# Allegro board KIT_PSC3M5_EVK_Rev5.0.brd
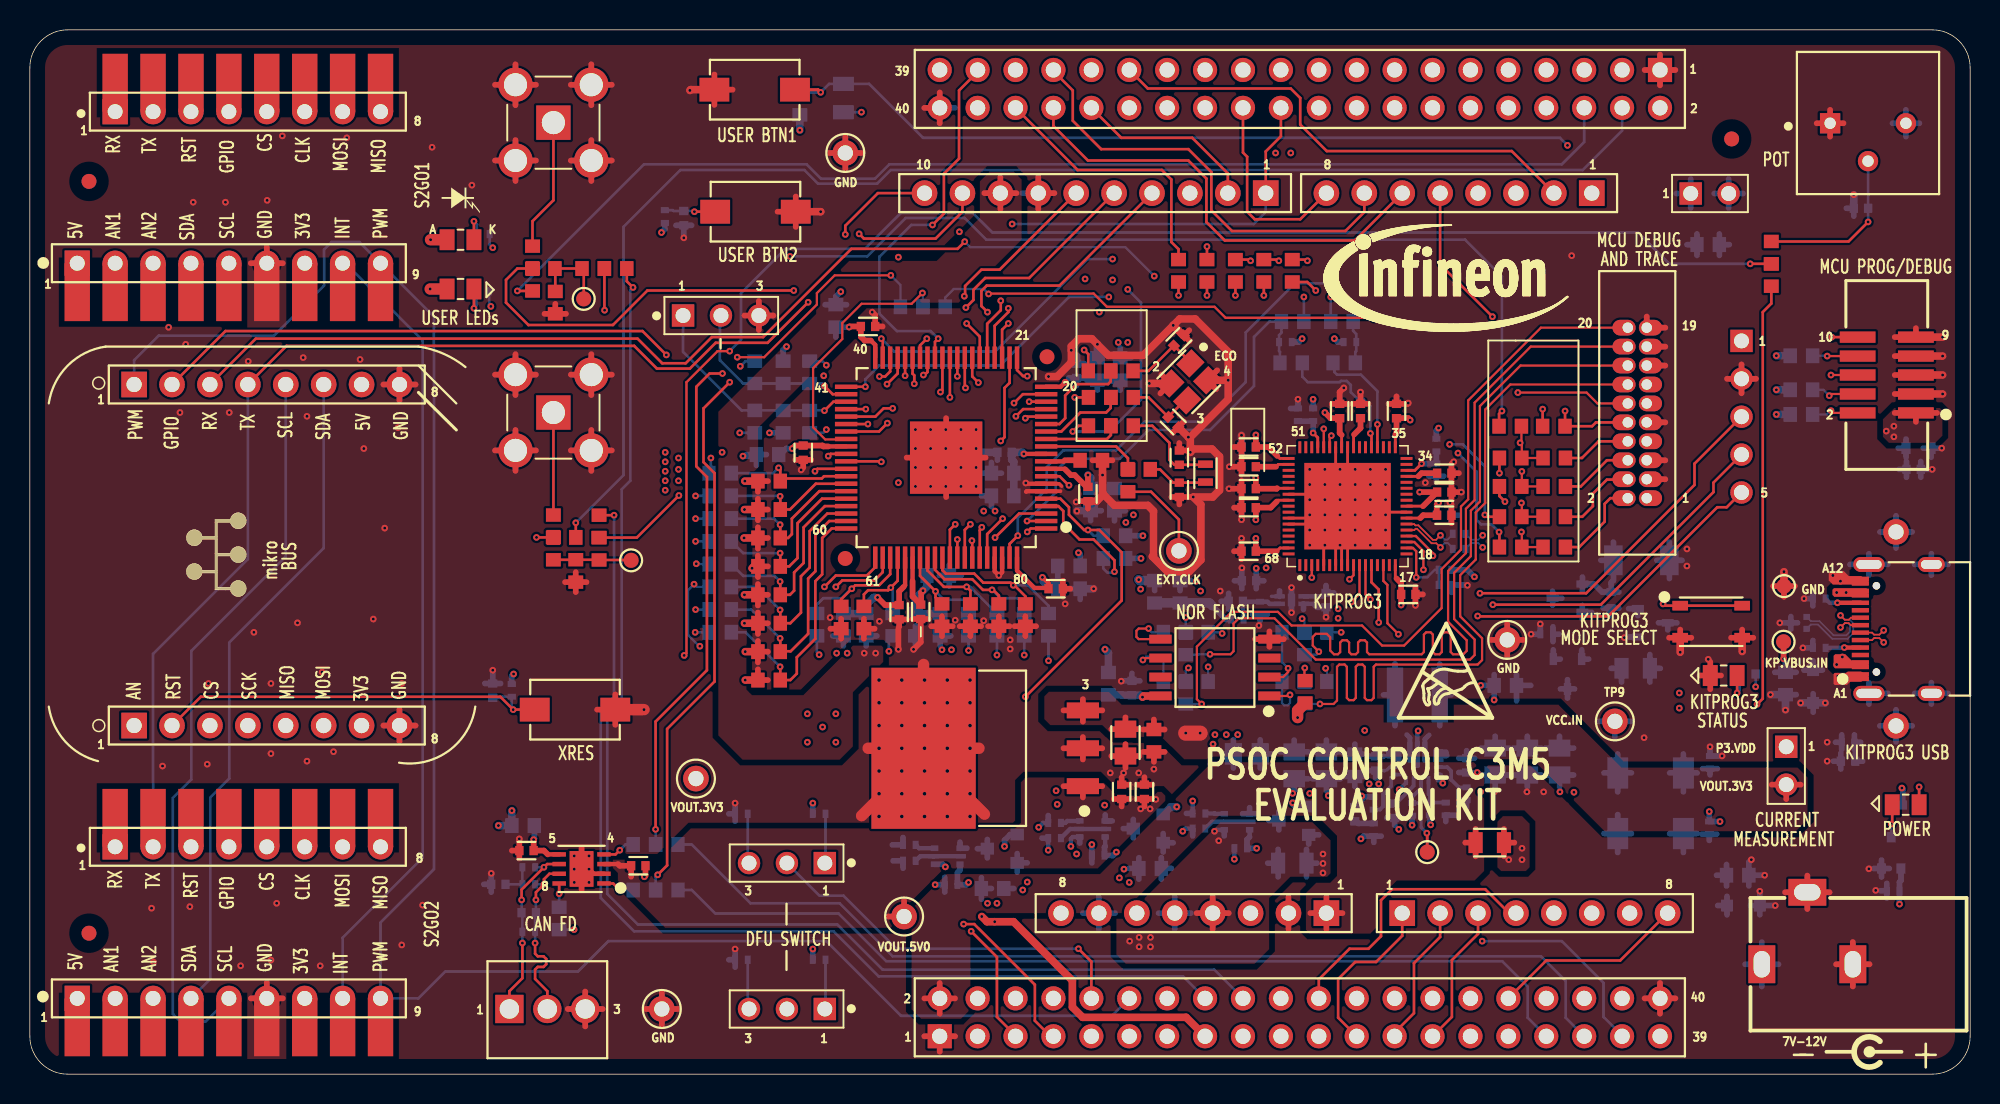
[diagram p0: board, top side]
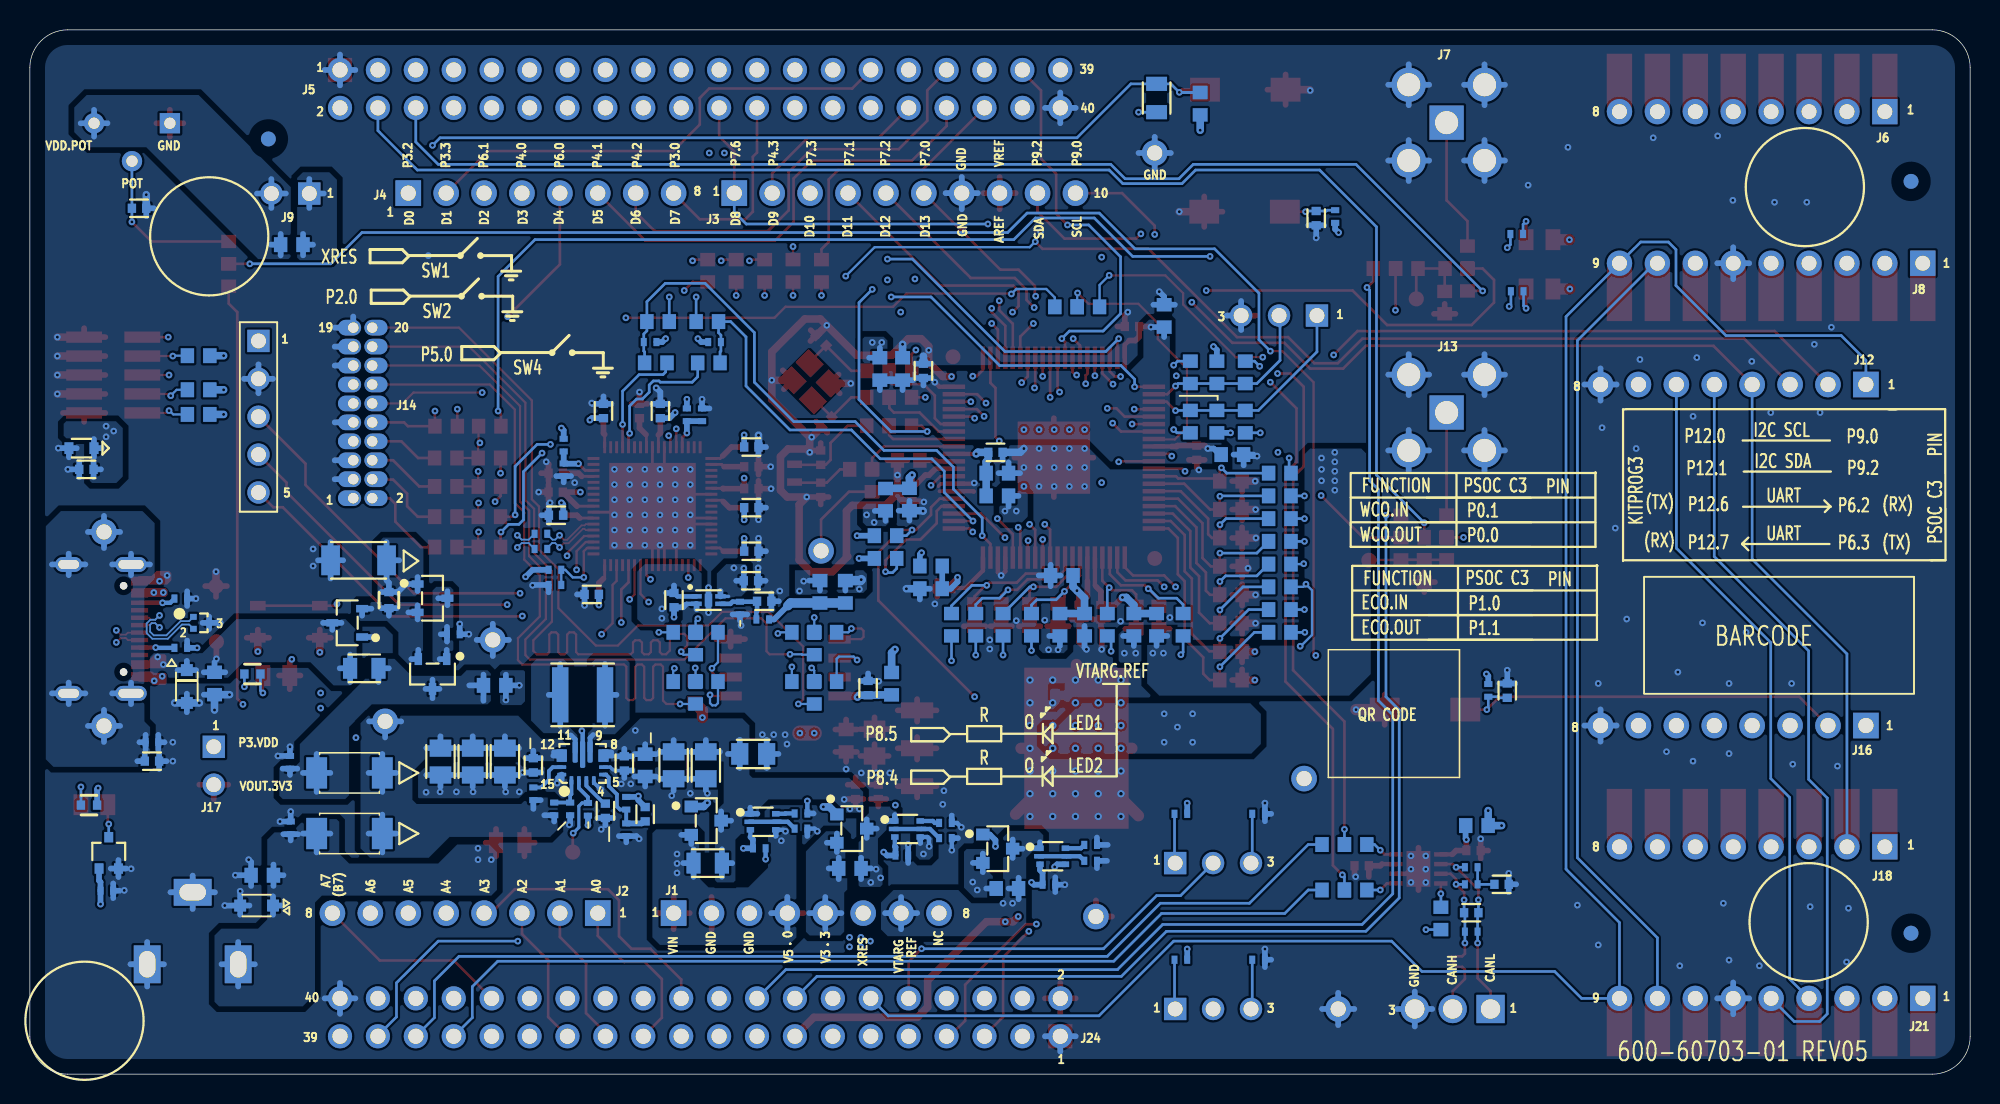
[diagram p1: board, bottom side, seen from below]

Outline 130 x 70 mm; copper layers: TOP, L02_GND, L03_SIG1, L04_SIG2, L05_PWR, BOTTOM. Coordinates in mm from the lower left corner of the outline.
Outline path: 0,67.46 0,2.54 arc(0.74,0.74) 2.54,0 127.46,0 arc(129.26,0.74) 130,2.54 130,67.46 arc(129.26,69.26) 127.46,70 2.54,70 arc(0.74,69.26) 0,67.46

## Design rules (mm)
constraint set DEFAULT: min track width 0.178
net group DIFFPAIR0: nets KP_USB_DM KP_USB_DP
net group DP1: nets N22087991 N22087993
net group POWER_PH: nets P5LP_VCCD P5LP_VDD
net group CS_MOSI_MISO_SPICLKMCU: nets CS MISO MOSI SPI_CLK_MCU
net group ETM: nets ETM_TRACE_CLK ETM_TRACE_D0 ETM_TRACE_D1 ETM_TRACE_D2 ETM_TRACE_D3
net group SPI_FLASH: nets SPI_CLK_FLASH SPI_CS_FLASH SPI_MISO_FLASH SPI_MOSI_FLASH
nets with their own width: min track width 0.178; nets P5LP_SWCLK P5LP_SWDIO
nets with their own width: min track width 0.254; nets GND_EARTH HDR_3V3 P5LP_SIO_VREF VDD_POT VDDA VIN VTARG_MEAS
nets with their own width: min track width 0.635; nets KP_VBUS
nets with their own width: min track width 0.762; nets GND_SIGNAL HDR_5V0 VDDD VOUT_3V3 VREFH VTARG_DEBUG VTARG_REF
nets with their own width: min track width 2.007; nets VIN_EXP

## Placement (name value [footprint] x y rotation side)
C1  1uF  [CAPC1608_0603N]  35.2 51.71 90 top
C2  0.1uF  [CAPC1005_0402N]  56.16 50.12 0 top
C3  18pF  [CAPC1005_0402N]  76.99 49.17 45 top
C4  0.1uF  [CAPC1005_0402N]  87.76 44.45 90 top
C5  1uF  [CAPC1005_0402N]  89.15 44.45 90 top
C6  0.1uF  [CAPC1005_0402N]  91.57 44.45 90 top
C7  18pF  [CAPC1005_0402N]  76.61 43.71 135 top
C8  0.1uF  [CAPC1005_0402N]  81.66 42.04 180 top
C9  0.1uF  [CAPC1005_0402N]  51.82 41.66 270 top
C10  22pF  [CAPC1005_0402N]  77.01 41.33 270 top
C11  4.7uF  [CAPC1608_0603N]  71.12 41.15 0 top
C12  1uF  [CAPC1005_0402N]  81.66 40.72 180 top
C13  1uF  [CAPC1005_0402N]  94.77 40.28 0 top
C14  0.1uF  [CAPC1608_0603N]  49.53 39.75 0 top
C15  0.1uF  [CAPC1005_0402N]  81.66 39.24 180 top
C16  22pF  [CAPC1005_0402N]  77.01 39.17 90 top
C17  1uF  [CAPC1005_0402N]  94.77 39.01 0 top
C18  0.1uF  [CAPC1005_0402N]  70.89 38.89 270 top
C19  0.1uF  [CAPC1608_0603N]  49.53 37.85 0 top
C20  0.1uF  [CAPC1005_0402N]  81.66 37.97 180 top
C21  0.1uF  [CAPC1005_0402N]  94.77 37.47 0 top
C22  0.1uF  [CAPC1608_0603N]  49.53 35.94 0 top
C23  0.1uF  [CAPC1005_0402N]  81.66 35.05 180 top
C24  0.1uF  [CAPC1608_0603N]  49.53 34.04 0 top
C25  1uF  [CAPC1608_0603N]  36.58 33.73 90 top
C26  0.1uF  [CAPC1608_0603N]  49.53 32.13 0 top
C27  0.1uF  [CAPC1005_0402N]  68.73 32.54 0 top
C28  0.1uF  [CAPC1005_0402N]  92.35 32.16 0 top
C29  0.1uF  [CAPC1608_0603N]  49.53 30.23 0 top
C30  0.1uF  [CAPC1005_0402N]  59.69 30.99 270 top
C31  0.1uF  [CAPC1608_0603N]  54.36 30.61 90 top
C32  0.1uF  [CAPC1608_0603N]  55.88 30.61 90 top
C33  0.1uF  [CAPC1608_0603N]  61.11 30.78 90 top
C34  0.1uF  [CAPC1608_0603N]  63.02 30.78 90 top
C35  0.1uF  [CAPC1608_0603N]  64.92 30.78 90 top
C36  0.1uF  [CAPC1608_0603N]  66.7 30.78 90 top
C37  0.22uF  [CAPC1005_0402N]  58.24 30.96 270 top
C38  0.1uF  [CAPC1608_0603N]  49.53 28.32 0 top
C39  0.1uF  [CAPC1608_0603N]  49.53 26.42 0 top
C40  0.1uF  [CAPC1005_0402N]  33.27 14.99 0 top
C41  0.1uF  [CAPC1005_0402N]  40.77 13.97 180 top
C42  0.1uF  [CAPC1005_0402N]  122.68 58.04 180 bottom
C43  0.1uF  [CAPC1005_0402N]  43.81 57.38 270 bottom
C44  1uF  [CAPC1608_0603N]  54 50.83 90 bottom
C45  1uF  [CAPC1608_0603N]  71.53 47.27 90 bottom
C46  0.1uF  [CAPC1005_0402N]  70.13 47.14 90 bottom
C47  1uF  [CAPC1005_0402N]  91.57 44.45 90 bottom
C48  1uF  [CAPC1005_0402N]  87.76 44.45 90 bottom
C49  1uF  [CAPC1005_0402N]  81.66 42.04 180 bottom
C50  0.1uF  [CAPC1005_0402N]  65.3 41.68 180 bottom
C51  1uF  [CAPC1608_0603N]  49.43 41.53 180 bottom
C52  1uF  [CAPC1005_0402N]  126.21 40.54 0 bottom
C53  1uF  [CAPC1608_0603N]  65.18 40.28 180 bottom
C54  10uF  [CAPC1608_0603N]  71.07 38.52 270 bottom
C55  1uF  [CAPC1005_0402N]  81.66 37.97 180 bottom
C56  1uF  [CAPC1005_0402N]  94.74 37.47 0 bottom
C57  1uF  [CAPC1005_0402N]  81.66 35.05 180 bottom
C58  0.1uF  [CAPC1005_0402N]  81.69 33.07 180 bottom
C59  1uF  [CAPC1608_0603N]  69.62 32.54 0 bottom
C60  1uF  [CAPC1005_0402N]  92.35 32.16 0 bottom
C61  0.1uF  [CAPC1005_0402N]  86.84 31.78 270 bottom
C62  0.1uF  [CAPC1005_0402N]  80.8 31.7 180 bottom
C63  10uF  [CAPC1608_0603N]  59.33 30.12 270 bottom
C65  10uF  [CAPC1608_0603N]  117.63 26.19 270 bottom
C66  0.1uF  [CAPC1005_0402N]  73.84 25.88 270 bottom
C67  0.1uF  [CAPC1005_0402N]  31.01 25.71 90 bottom
C79  10nF  [CAPC1005_0402N]  121.82 20.98 180 bottom
C80  10uF  [CAPC2012_0805N]  102.49 20.95 270 bottom
C81  10uF  [CAPC2012_0805N]  100.33 20.95 270 bottom
C82  10uF  [CAPC2012_0805N]  98.17 20.95 270 bottom
C83  0.1uF  [CAPC1005_0402N]  90.17 20.83 270 bottom
C84  0.1uF  [CAPC1005_0402N]  96.27 20.7 270 bottom
C85  10uF  [CAPC1608_0603N]  88.77 20.7 270 bottom
C86  22uF  [CAPC2012_0805N]  86.87 20.7 270 bottom
C87  22uF  [CAPC2012_0805N]  84.71 20.7 270 bottom
C88  22uF  [CAPC2012_0805N]  81.53 21.46 180 bottom
C90  0.1uF  [CAPC1005_0402N]  91.44 17.65 270 bottom
C91  22pF  [CAPC1005_0402N]  88.77 17.42 270 bottom
C92  1uF  [CAPC1608_0603N]  114.43 13.34 0 bottom
C93  100pF  [CAPC1005_0402N]  31.39 12.73 180 bottom
C94  100pF  [CAPC1005_0402N]  33.43 10.82 180 bottom
C95  0.47uF  [CAPC1005_0402N]  74.68 18.92 90 top
C96  1uF  [CAPC1005_0402N]  73.15 18.92 90 top
C97  10uF  [CAPC1608_0603N]  75.31 22.35 270 top
C98  33uF  [CAPC2012_0805N]  73.41 22.23 270 top
D1  ESD5V0D5-TP  [SODFL1608X77M]  126.54 41.96 180 bottom
D2  TLZ5V1A-GS08  [DIOMELF3515N]  107.98 34.44 0 bottom
D3  SD05-7  [DIO2_SOD323N]  119.48 25.98 90 bottom
D4  PMEG3030EP  [DIO_NXP_SOD-128]  108.58 20.19 0 bottom
D5  PMEG3030EP  [DIO_NXP_SOD-128]  108.58 16.13 0 bottom
D6  ESD12VD3B-TP  [DIO2_SOD323_BIQ]  114.81 11.3 180 bottom
FB1  1K  [INDC1608_0603N]  72.67 38.51 90 bottom
FB2  1K  [INDC1608_0603N]  60.99 30.12 90 bottom
J1  CON 8  [RTST254P1X08_W265]  86.87 10.79 180 top
J2  CON 8  [RTST254P1X08_W265]  91.95 10.79 0 top
J3  CON 10  [RTST254P1X10_W265]  82.8 59.05 180 top
J4  CON 8  [RTST254P1X08_W265]  104.65 59.05 180 top
J5  61304021821  [WURTH_61304021821]  109.22 67.31 180 top
J6  CON 8  [RTST254P1X08_W265_VER1]  5.71 64.52 0 top
J7  733910070  [MOL_SMA73391007X]  35.08 63.78 0 top
J8  CON 9  [SULLINS_PPPC091LFBN-RC_VER1]  3.17 54.36 0 top
J9  HDR 2  [CTST254P1X02_W260]  111.28 59.03 0 top
J10  HDR 3  [CTST254P1X03_W260]  43.76 50.85 0 top
J11  HDR 5x2  [FCI_20021521-00010T1LF]  126.36 44.32 90 top
J12  CON 8  [RTST254P1X08_W265]  6.99 46.23 0 top
J13  733910070  [MOL_SMA73391007X]  35.08 44.35 0 top
J14  HDR 10x2  [CNC_3220-20-0100-00]  108.33 38.61 90 top
J15  629722000214  [GCT_USB4105-GF-A]  126.32 29.85 90 top
J16  CON 8  [RTST254P1X08_W265]  6.99 23.37 0 top
J17  HDR 2  [CTST254P1X02_W260]  117.68 21.95 270 top
J18  CON 8  [RTST254P1X08_W265_VER1]  5.71 15.24 0 top
J19  HDR 3  [CTST254P1X03_W260]  53.26 14.15 180 top
J20  PWR_JACK  [CUI_PJ-102A]  116.04 7.37 0 top
J21  CON 9  [SULLINS_PPPC091LFBN-RC_VER1]  3.17 5.08 0 top
J22  HDR 3  [CTST254P1X03_W260]  53.26 4.37 180 top
J23  691210910003  [OST_OSTVN03A150]  32.13 4.37 0 top
J24  61304021821  [WURTH_61304021821]  60.96 2.54 0 top
J25  HDR 5  [CTST254P1X05_W260]  114.68 49.15 270 bottom
JMP1  USB_Hold  [CON_RA_STIFF_1000P]  125.03 23.35 90 top
L1  1.5uH  [PULSE_PA4332]  92.96 25.43 90 bottom
LED1  BLUE  [LEDC2012_0805_BLUE]  28.85 55.93 180 top
LED2  Yellow LED  [LEDC2012_0805]  28.85 52.63 180 top
LED3  Yellow LED  [LEDC2012_0805]  113.49 26.72 0 top
LED4  RED  [LEDC2012_0805]  125.68 18.06 0 top
NOREF  -  []  162.49 68.66 90 top
NOREF#2  -  []  54.69 46.08 0 top
NOREF#3  -  []  203.65 115.42 0 top
NOREF#4  -  []  124.02 -12.29 0 top
NOREF#5  -  []  56.83 16.64 90 top
NOREF#6  -  []  38.31 9.31 0 top
NOREF#7  -  []  60.96 2.54 90 top
NOREF#8  -  []  83.82 67.31 0 top
NOREF#9  -  []  122.64 28.1 90 top
NOREF#10  -  []  129.23 69.28 0 top
NOREF#11  -  []  60.96 67.31 0 top
NOREF#12  -  []  79.39 35.33 90 top
NOREF#13  -  []  38.31 9.31 0 top
NOREF#14  -  []  75.75 29.16 0 top
NOREF#15  -  []  56.83 16.64 0 top
NOREF#16  -  [unnamed#2]  3.96 59.84 0 top
NOREF#17  -  []  110.89 1.19 90 top
NOREF#18  -  []  35.46 14.73 0 top
NOREF#19  -  []  -9.63 -34.14 0 top
NOREF#20  -  []  -11.43 -23.16 0 top
NOREF#21  -  []  38.46 12.78 90 top
NOREF#22  -  []  83.82 2.54 0 top
NOREF#23  -  []  70.55 21.84 90 top
NOREF#24  -  []  63.37 18.9 0 top
NOREF#25  -  []  0 0 90 top
NOREF#26  -  []  122.65 25.38 0 top
NOREF#27  -  []  60.96 2.54 0 top
NOREF#28  -  []  123.22 25.53 0 top
NOREF#29  -  []  127.4 25.53 90 top
NOREF#30  -  []  119.38 71.12 0 top
NOREF#31  -  [unnamed#2]  114.02 62.69 0 top
NOREF#32  -  []  113.77 298.25 0 top
NOREF#33  -  []  110.89 73.89 0 top
NOREF#34  -  []  122.64 28.6 90 top
NOREF#35  -  []  76.76 24.61 90 top
NOREF#36  -  []  67.39 35.33 0 top
NOREF#37  -  []  131.59 18.03 90 top
NOREF#38  -  []  131.59 18.03 90 top
NOREF#39  -  []  83.05 26.62 90 top
NOREF#40  -  []  76.76 24.61 0 top
NOREF#41  -  []  59.29 6.43 0 top
NOREF#42  -  []  68.09 41.08 90 top
NOREF#43  -  []  0 70 0 top
NOREF#44  -  []  109.22 64.77 90 top
NOREF#45  -  []  -292.35 -210.03 0 top
NOREF#46  -  []  42.16 65 0 top
NOREF#47  -  []  58.1 21.84 0 top
NOREF#48  -  []  96.8 143.36 0 top
NOREF#49  -  [unnamed#2]  3.96 9.45 0 top
NOREF#50  -  []  -29.59 22.1 180 bottom
NOREF#51  -  [unnamed#2]  3.96 59.84 180 bottom
NOREF#52  -  []  -34.42 19.05 180 bottom
NOREF#53  -  [unnamed#2]  114.02 62.69 180 bottom
NOREF#54  -  [unnamed#2]  3.96 9.45 180 bottom
NOREF#55  -  []  -137.87 -9.3 180 bottom
NOREF#56  -  []  -98.83 1.05 180 bottom
Q1  PMV48XP,215  [SOT95P230X110-3N]  103.02 31.9 270 bottom
Q2  PMV48XP,215  [SOT95P230X110-3N]  108.74 30.25 90 bottom
Q3  PMV48XP,215  [SOT95P230X110-3N]  103.02 26.82 0 bottom
Q4  DMG2301L-7  [SOT23_G_S_D-DIODES]  84.68 16.99 270 bottom
Q5  DMG2301L-7  [SOT23_G_S_D-DIODES]  74.93 16.46 270 bottom
Q6  BCM857BV,115  [SOT666_6N-NXP]  80.87 16.92 270 bottom
Q7  BCM857BV,115  [SOT666_6N-NXP]  71.2 16.43 270 bottom
Q8  DMG2301L-7  [SOT23_G_S_D-DIODES]  65.15 15.11 270 bottom
Q9  BCM857BV,115  [SOT666_6N-NXP]  61.47 14.61 270 bottom
Q10  NX3020NAKW,115  [SOT323_SC70-3N_NXP]  124.71 14.83 180 bottom
R1  10K  [TRIM_3386P-1-103TLF]  120.62 63.74 0 top
R2  0 Ohm  [RESC1608_0603N]  116.68 55.07 270 top
R3  0 Ohm  [RESC1608_0603N]  116.68 53.57 90 top
R4  0 Ohm  [RESC1608_0603N]  33.68 54.75 270 top
R5  10K  [RESC1608_0603N]  34.43 54 180 top
R6  0 Ohm  [RESC1608_0603N]  37.74 54 180 top
R7  0 Ohm  [RESC1608_0603N]  39.24 54 180 top
R8  0 Ohm  [RESC1608_0603N]  33.68 53.25 90 top
R9  0 Ohm  [RESC1608_0603N]  78.87 53.85 270 top
R10  0 Ohm  [RESC1608_0603N]  77.45 25.56 90 bottom
R11  0 Ohm  [RESC1608_0603N]  80.77 53.85 270 top
R12  0 Ohm  [RESC1608_0603N]  85.4 28.87 90 bottom
R13  0 Ohm  [RESC1608_0603N]  71.67 47.14 0 top
R14  0 Ohm  [RESC1608_0603N]  73.17 47.14 0 top
R15  0 Ohm  [RESC1608_0603N]  82.68 53.85 270 top
R16  0 Ohm  [RESC1608_0603N]  77.45 28.87 90 bottom
R17  0 Ohm  [RESC1608_0603N]  71.68 45.36 180 top
R18  0 Ohm  [RESC1608_0603N]  73.18 45.36 180 top
R19  0 Ohm  [RESC1608_0603N]  84.58 53.85 270 top
R20  0 Ohm  [RESC1608_0603N]  85.4 25.56 90 bottom
R21  0 Ohm  [RESC1608_0603N]  71.68 43.46 180 top
R22  0 Ohm  [RESC1608_0603N]  73.18 43.46 0 top
R23  0 Ohm  [RESC1608_0603N]  76.96 53.85 270 top
R24  0 Ohm  [RESC1608_0603N]  60.58 51.44 180 bottom
R25  0 Ohm  [RESC1608_0603N]  102.11 43.43 180 top
R26  0 Ohm  [RESC1608_0603N]  74.32 40.54 0 top
R27  0 Ohm  [RESC1608_0603N]  73.57 39.79 270 top
R28  0 Ohm  [RESC1608_0603N]  99.21 41.3 0 top
R29  0 Ohm  [RESC1608_0603N]  102.13 41.3 180 top
R30  0 Ohm  [RESC1608_0603N]  99.21 39.4 0 top
R31  0 Ohm  [RESC1608_0603N]  102.13 39.4 180 top
R32  0 Ohm  [RESC1608_0603N]  35.08 36.73 270 top
R33  0 Ohm  [RESC1608_0603N]  38.14 36.72 270 top
R34  0 Ohm  [RESC1608_0603N]  35.83 35.98 180 top
R35  10K  [RESC1608_0603N]  35.08 35.23 90 top
R36  0 Ohm  [RESC1608_0603N]  38.14 35.22 270 top
R37  0 Ohm  [RESC1608_0603N]  99.21 37.36 0 top
R38  0 Ohm  [RESC1608_0603N]  102.13 37.36 180 top
R39  0 Ohm  [RESC1608_0603N]  99.21 35.33 0 top
R40  0 Ohm  [RESC1608_0603N]  102.13 35.33 180 top
R41  10K  [RESC1608_0603N]  85.45 25.63 90 top
R42  0 OHM  [RESC2012X60N]  97.82 15.52 180 top
R43  10K  [RESC1608_0603N]  51.59 65.05 90 bottom
R44  4.7K  [RESC1005_0402N]  42.55 57.49 90 bottom
R45  2.7K  [RESC1005_0402N]  30.38 56.31 0 bottom
R46  390 OHM  [RESC1005_0402N]  30.35 52.48 0 bottom
R47  0 Ohm  [RESC1608_0603N]  87.91 50.44 180 bottom
R48  0 Ohm  [RESC1608_0603N]  84.61 50.44 0 bottom
R49  0 Ohm  [RESC1608_0603N]  112.45 55.6 0 bottom
R50  4.7K  [RESC1005_0402N]  88.44 49.07 180 bottom
R51  4.7K  [RESC1005_0402N]  84.12 49.07 0 bottom
R52  10K  [RESC1608_0603N]  118.69 48.16 180 bottom
R53  0 Ohm  [RESC1608_0603N]  88.06 47.68 0 bottom
R54  0 Ohm  [RESC1608_0603N]  84.51 47.68 180 bottom
R55  0 Ohm  [RESC1608_0603N]  73.05 47.27 90 bottom
R56  0 Ohm  [RESC1608_0603N]  52.25 47.04 270 bottom
R57  10K  [RESC1608_0603N]  50.47 47.04 90 bottom
R58  0 Ohm  [RESC1608_0603N]  48.56 47.04 270 bottom
R59  10K  [RESC1608_0603N]  118.69 45.87 180 bottom
R60  10K  [RESC1608_0603N]  118.69 44.22 180 bottom
R61  49.9K  [RESC1005_0402N]  85.98 44.2 270 bottom
R62  49.9K  [RESC1005_0402N]  84.96 44.2 270 bottom
R63  0 Ohm  [RESC1608_0603N]  52.25 43.74 90 bottom
R64  10K  [RESC1608_0603N]  50.47 43.74 270 bottom
R65  0 Ohm  [RESC1608_0603N]  48.56 43.74 90 bottom
R66  15K  [RESC1005_0402N]  94.23 42.16 270 bottom
R67  30K  [RESC1005_0402N]  94.23 40.51 90 bottom
R68  0 Ohm  [RESC1608_0603N]  46.25 40.28 180 bottom
R69  0 Ohm  [RESC1608_0603N]  65.18 38.76 180 bottom
R70  0 Ohm  [RESC1608_0603N]  46.25 38.76 180 bottom
R71  0 Ohm  [RESC1608_0603N]  46.25 37.24 180 bottom
R72  22 OHM  [RESC1005_0402N]  95.76 36.22 180 bottom
R73  10K  [RESC1608_0603N]  72.67 36.09 180 bottom
R74  0 Ohm  [RESC1608_0603N]  46.25 35.71 180 bottom
R75  22 OHM  [RESC1005_0402N]  95.76 35.2 180 bottom
R76  10K  [RESC1608_0603N]  72.67 34.57 180 bottom
R77  0 Ohm  [RESC1608_0603N]  46.25 34.19 180 bottom
R78  0 Ohm  [RESC1608_0603N]  69.62 34.06 0 bottom
R79  15K  [RESC1005_0402N]  94.82 33.81 180 bottom
R80  0 Ohm  [RESC1608_0603N]  60.86 33.43 0 bottom
R81  30K  [RESC1005_0402N]  94.82 32.79 180 bottom
R82  0 Ohm  [RESC1608_0603N]  46.25 32.66 180 bottom
R83  5.1K  [RESC1005_0402N]  119.89 31.88 180 bottom
R84  330 OHM  [RESC1005_0402M]  105.94 31.78 270 bottom
R85  0 Ohm  [RESC1608_0603N]  46.25 31.14 180 bottom
R86  100K  [RESC1005_0402N]  80.9 30.48 180 bottom
R87  0 Ohm  [RESC1608_0603N]  68.25 30.12 270 bottom
R88  0 Ohm  [RESC1608_0603N]  66.62 30.12 270 bottom
R89  0 Ohm  [RESC1608_0603N]  64.8 30.12 270 bottom
R90  0 Ohm  [RESC1608_0603N]  62.89 30.12 270 bottom
R91  0 Ohm  [RESC1608_0603N]  57.81 30.12 270 bottom
R92  0 Ohm  [RESC1608_0603N]  56.03 30.12 90 bottom
R93  0 Ohm  [RESC1608_0603N]  54.51 30.12 90 bottom
R94  0 Ohm  [RESC1608_0603N]  52.73 30.12 270 bottom
R95  0 Ohm  [RESC1608_0603N]  78.2 29.62 180 bottom
R96  33 OHM  [RESC1608_0603N]  76.7 29.62 180 bottom
R97  0 Ohm  [RESC1608_0603N]  46.25 29.62 180 bottom
R98  10K  [RESC1005_0402N]  101.63 29.49 0 bottom
R99  5.1K  [RESC1005_0402N]  119.89 28.57 180 bottom
R100  0 Ohm  [RESC1608_0603N]  78.2 26.31 180 bottom
R101  33 OHM  [RESC1608_0603N]  76.7 26.31 180 bottom
R102  0 OHM  [RESC2012X60N]  107.59 27.2 180 bottom
R104  0 Ohm  [RESC1608_0603N]  86.15 29.62 180 bottom
R105  33 OHM  [RESC1608_0603N]  84.65 29.62 180 bottom
R106  750 OHM  [RESC1005_0402M]  115.09 26.82 0 bottom
R107  0 Ohm  [RESC1608_0603N]  72.26 26.17 90 bottom
R108  0 Ohm  [RESC1608_0603N]  98.86 26.06 0 bottom
R109  4.7K  [RESC1005_0402N]  32.28 25.72 270 bottom
R113  0 Ohm  [RESC1608_0603N]  86.15 26.31 180 bottom
R114  33 OHM  [RESC1608_0603N]  84.65 26.31 180 bottom
R115  100K  [RESC1005_0402N]  121.82 22.25 0 bottom
R116  220 OHM  [RESC1005_0402M]  126.03 18.03 0 bottom
R117  100K  [RESC1005_0402N]  112.57 20.9 90 bottom
R121  10K  [RESC1005_0402N]  96.27 18.8 270 bottom
R123  681K  [RESC1005_0402N]  90.04 18.16 270 bottom
R124  10K  [RESC1005_0402N]  94.87 17.78 90 bottom
R125  10K  [RESC1005_0402N]  93.8 17.78 90 bottom
R126  100K  [RESC1005_0402N]  92.61 17.75 90 bottom
R127  10K  [RESC1005_0402N]  78.33 17.48 180 bottom
R128  1K  [RESC1005_0402N]  52.88 17.45 0 bottom
R129  1K  [RESC1005_0402N]  47.68 17.45 180 bottom
R130  10K  [RESC1005_0402N]  68.66 16.84 180 bottom
R131  0 Ohm  [RESC1608_0603N]  33.05 16.66 180 bottom
R132  100K  [RESC1005_0402N]  112.52 16.51 90 bottom
R133  100K  [RESC1005_0402N]  78.33 16.46 0 bottom
R134  130K  [RESC1005_0402N]  90.04 16.38 90 bottom
R135  100K  [RESC1005_0402N]  68.66 15.82 0 bottom
R136  0 Ohm  [RESC1608_0603N]  42.67 15.39 0 bottom
R137  0 Ohm  [RESC1608_0603N]  41.17 15.39 0 bottom
R138  10K  [RESC1005_0402N]  58.93 15.37 180 bottom
R139  10K  [RESC1005_0402N]  81.13 15.14 180 bottom
R140  10K  [RESC1005_0402N]  71.58 14.66 180 bottom
R141  0 Ohm  [RESC1608_0603N]  75.06 13.79 0 bottom
R142  100K  [RESC1005_0402N]  58.93 14.3 0 bottom
R143  0 OHM  [RESC2012X60N]  84.58 14.15 0 bottom
R144  60.4 OHM  [RESC1005_0402N]  33.43 13.87 180 bottom
R145  60.4 OHM  [RESC1005_0402N]  33.43 12.73 0 bottom
R146  10K  [RESC1005_0402N]  61.72 12.7 180 bottom
R147  0 Ohm  [RESC1608_0603N]  64.5 12.45 0 bottom
R148  0 Ohm  [RESC1608_0603N]  42.67 12.34 0 bottom
R149  0 Ohm  [RESC1608_0603N]  41.17 12.34 0 bottom
R150  100K  [RESC1005_0402N]  124.84 12.29 0 bottom
R151  0 Ohm  [RESC1608_0603N]  35.46 10.44 90 bottom
R152  120 OHM  [RESC1005_0402N]  33.43 9.55 0 bottom
R153  1K  [RESC1005_0402N]  52.88 7.67 0 bottom
R154  1K  [RESC1005_0402N]  47.68 7.67 180 bottom
R155  100K  [RESC1005_0402N]  82.42 31.24 90 bottom
R156  0 Ohm  [RESC1608_0603N]  77.06 32.33 90 bottom
R157  0 Ohm  [RESC1608_0603N]  75.36 32.33 90 bottom
R158  0 Ohm  [RESC1608_0603N]  99.19 43.43 0 top
R159  0 Ohm  [RESC1608_0603N]  59.08 51.44 0 bottom
R160  0 OHM  [RESC2012X60N]  54.51 65.43 270 bottom
SW1  EVQ-PE105K  [SW_EVQ-PE105K]  36.53 24.43 0 top
SW2  EVQ-PNF04M  [SW_EVQ-PE105K]  48.62 57.81 180 top
SW3  434123025826  [SW_SKRPACE010]  112.65 30.33 0 top
SW4  EVQ-PNF04M  [SW_EVQ-PE105K]  48.56 65.99 180 top
TP1  BLACK  [TPT_KEY_5000]  54.64 61.75 0 top
TP3  TP_SMD  [TP102C]  37.11 51.97 0 top
TP4  RED  [TPT_KEY_5000]  76.99 35.08 180 top
TP5  TP_SMD  [TP102C]  40.28 34.44 0 top
TP6  TP_SMD  [TP102C]  117.53 32.72 90 top
TP7  TP_SMD  [TP102C]  117.5 28.98 90 top
TP8  BLACK  [TPT_KEY_5000]  98.98 29.11 0 top
TP9  RED  [TPT_KEY_5000]  106.2 23.65 180 top
TP10  RED  [TPT_KEY_5000]  44.63 19.81 270 top
TP11  TP_SMD  [TP102C]  93.62 14.88 180 top
TP12  RED  [TPT_KEY_5000]  58.57 10.57 270 top
TP13  BLACK  [TPT_KEY_5000]  42.34 4.37 0 top
U1  PSC3M5FDS2AFQ1  [LQFP50P1400X1400X160-81N]  61.39 41.33 180 top
U2  CY8C5868LTI-LP039  [QFN40P800X800_68-H580N]  88.29 38.07 90 top
U3  S25FL128LAGMFV013  [SOIC127P800X216-8N]  79.4 27.25 180 top
U4  TLE9251VLEXUMA1  [SON65P300X300X110-8N_TP]  36.96 13.76 180 top
U5  SIP32408DNP-T1-GE4  [TDFN50P160X120_4-HS86X50M]  84.53 31.78 180 bottom
U7  ESD5V3U2U-03F  [SOTFL40P120X59-3N]  118.52 30.25 180 bottom
U8  TPS63070RNMT  [QFN50P250X300X100-15M_NOFID]  92.96 20.83 90 bottom
U9  LM3940IS-3.3/NOPB  [TO254P1524X483-4N_TI]  64.01 21.84 180 top
Y1  16MHz  [OSCCC200X250X90-4M]  77.65 46.41 225 top
Y2  32.768kHz  [XTAL_ABS05_1M6X1M]  78.77 40.28 90 top

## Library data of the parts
C1 C11 C14 C19 C22 C24-C26 C29 C31-C36 C38 C39 C44 C45 C51 C53 C54 C59 C63 C65 C85 C92 C97 = CAP-NP: User Part Number: Part No
C2-C10 C12 C13 C15-C18 C20 C21 C23 C27 C28 C30 C37 C40-C43 C46-C50 C52 C55-C58 C60-C62 C66 C67 C79-C84 C86-C88 C90 C91 C93 C95 C96 C98 = CAP-NP
C94 = CAP-NP: signal model: CAP-NP_CAPC1005_0402N_DISCRETE_100PF_100pF
D1 D3 = DIO-TVS
D2 = DIO-ZENER
D4 D5 = DIO-SCHOTTKY: User Part Number: Part No
D6 = DIO-TVS-BI
FB1 FB2 = FB
J1 J2 J4 J6 J12 J16 J18 = SKT-8-ALT-J
J3 = SKT-10-J
J5 J24 = SKT-40-EVEN-ODD-J
J7 J13 = RF-4GND
J8 J21 = SKT-9-J
J9 J17 = PLG-2-J: User Part Number: Part No
J10 J19 J22 = PLG-3-J
J11 = PLG-10-ODD-EVEN-J
J14 = PLG-20-ODD-EVEN-J
J15 = USB_TYPE_C-16PIN_4SH
J20 = JACK-PWR-3P
J23 = OSTVN03A150
J25 = PLG-5-J
JMP1 = USB_HOLD
L1 = IND
LED1 = DIO-LED
LED2-LED4 = DIO-LED: User Part Number: Part No
Q1-Q5 Q8 = FET-MOS-P
Q6 Q7 Q9 = PNP-PNP-E1B1C2E2B2C1
Q10 = FET-MOS-N
R1 = POT_1_2_3
R2-R23 R25-R41 R43-R83 R85-R101 R104 R105 R107-R109 R113-R115 R117 R121 R123-R142 R146-R151 R153-R159 = RES: User Part Number: Part No
R24 = RES: User Part Number: Part No; signal model: RES_RESC1608_0603N_DISCRETE_0_OHM_0_OHM
R42 R84 R102 R106 R116 R143 R160 = RES
R144 R145 = RC0402FR-0760R4L: User Part Number: Part No; signal model: RC0402FR-0760R4L_RESC1005_0402N_60.4_OHM_60.4_OHM
R152 = ERJ-3GEYJ121V: User Part Number: Part No; signal model: ERJ-3GEYJ121V_RESC1005_0402N_120_OHM_120_OHM
SW1 = SWITCH-PB-A-B_3
SW2 = SWITCH-PB-1-2_4
SW3 = SWITCH-PB-12-34
SW4 = SWITCH-PB-1-2_3
TP1 TP4 TP8-TP10 TP12 TP13 = TP
TP3 TP5-TP7 TP11 = TP_SMD
U1 = IC_PSC3M5FDS2AFQ1
U2 = CY8C5868LTI-LP039
U3 = IC_S25FL128LAG
U4 = TLE9251VLE
U5 = SIP32408
U7 = ESD5V3U2U-03F
U8 = TPS63000_3: room: room1
U9 = LDO-1IN_2-4GND_3OUT
Y1 = XTAL-4P-2G4G
Y2 = XTAL-2P

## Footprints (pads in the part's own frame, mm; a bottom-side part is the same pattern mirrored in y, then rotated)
CAPC1005_0402N
  rect 0.56x0.62 smd: 1(-0.48,0) 2(0.48,0)
CAPC1608_0603N
  rect 0.9x1 smd: 1(-0.75,0) 2(0.75,0)
CAPC2012_0805N
  rect 1.15x1.45 smd: 1(-0.9,0) 2(0.9,0)
CNC_3220-20-0100-00
  oval 1.05x1.55 hole 0.7: 1(0,0) 2(0,1.27) 3(1.27,0) 4(1.27,1.27) 5(2.54,0) 6(2.54,1.27) 7(3.81,0) 8(3.81,1.27) 9(5.08,0) 10(5.08,1.27) 11(6.35,0) 12(6.35,1.27) 13(7.62,0) 14(7.62,1.27) 15(8.89,0) 16(8.89,1.27) 17(10.16,0) 18(10.16,1.27) 19(11.43,0) 20(11.43,1.27)
CON_RA_STIFF_1000P
  round 1.72 hole 1.02: 1(0,0) 2(13,0)
CTST254P1X02_W260
  rect 1.5x1.5 hole 1: 1(0,0)
  round 1.5 hole 1: 2(2.54,0)
CTST254P1X03_W260
  rect 1.5x1.5 hole 1: 1(0,0)
  round 1.5 hole 1: 2(2.54,0) 3(5.08,0)
CTST254P1X05_W260
  rect 1.5x1.5 hole 1: 1(0,0)
  round 1.5 hole 1: 2(2.54,0) 3(5.08,0) 4(7.62,0) 5(10.16,0)
CUI_PJ-102A
  rect 1.8x2.54 hole 1.1x1.778: 1(0,0) 2(6.096,0)
  rect 2.54x1.8 hole 1.778x1.1: 3(3.048,4.826)
DIO2_SOD323_BIQ
  rect 0.8x0.8 smd: 1(1.1,0) 2(-1.1,0)
DIO2_SOD323N
  rect 0.8x0.8 smd: A(-1.1,0) K(1.1,0)
DIO_NXP_SOD-128
  rect 1.4x2.1 smd: A(2.2,0) K(-2.2,0)
DIOMELF3515N
  rect 1.25x2 smd: A(1.875,0) K(-1.875,0)
FCI_20021521-00010T1LF
  rect 0.76x2.4 smd: 1(0,0) 2(0,3.9) 3(1.27,0) 4(1.27,3.9) 5(2.54,0) 6(2.54,3.9) 7(3.81,0) 8(3.81,3.9) 9(5.08,0) 10(5.08,3.9)
GCT_USB4105-GF-A
  round 0.5 hole 0.65 unplated: (-2.89,2.605) (2.89,2.605)
  rect 0.3x1.15 smd: A1(-3.35,3.68) A4(-2.55,3.68) A5(-1.25,3.68) A6(-0.25,3.68) A7(0.25,3.68) A8(1.25,3.68) A9(2.55,3.68) A12(3.35,3.68) B1(3.05,3.68) B4(2.25,3.68) B5(1.75,3.68) B6(0.75,3.68) B7(-0.75,3.68) B8(-1.75,3.68) B9(-2.25,3.68) B12(-3.05,3.68)
  oval 1x2.1 hole 0.6x1.7: SH1(-4.32,3.105) SH2(4.32,3.105)
  oval 1x1.8 hole 0.6x1.4: SH3(-4.32,-1.075) SH4(4.32,-1.075)
INDC1608_0603N
  rect 0.9x1 smd: 1(-0.75,0) 2(0.75,0)
LEDC2012_0805
  rect 1x1.4 smd: A(0.9,0) K(-0.9,0)
LEDC2012_0805_BLUE
  rect 1x1.4 smd: A(0.9,0) K(-0.9,0)
LQFP50P1400X1400X160-81N
  round 1 smd: (-6.759,-6.759) (6.759,6.759)
  rect 1.5x0.3 smd: 1(-6.7,4.75) 2(-6.7,4.25) 3(-6.7,3.75) 4(-6.7,3.25) 5(-6.7,2.75) 6(-6.7,2.25) 7(-6.7,1.75) 8(-6.7,1.25) 9(-6.7,0.75) 10(-6.7,0.25) 11(-6.7,-0.25) 12(-6.7,-0.75) 13(-6.7,-1.25) 14(-6.7,-1.75) 15(-6.7,-2.25) 16(-6.7,-2.75) 17(-6.7,-3.25) 18(-6.7,-3.75) 19(-6.7,-4.25) 20(-6.7,-4.75) 41(6.7,-4.75) 42(6.7,-4.25) 43(6.7,-3.75) 44(6.7,-3.25) 45(6.7,-2.75) 46(6.7,-2.25) 47(6.7,-1.75) 48(6.7,-1.25) 49(6.7,-0.75) 50(6.7,-0.25) 51(6.7,0.25) 52(6.7,0.75) 53(6.7,1.25) 54(6.7,1.75) 55(6.7,2.25) 56(6.7,2.75) 57(6.7,3.25) 58(6.7,3.75) 59(6.7,4.25) 60(6.7,4.75)
  rect 0.3x1.5 smd: 21(-4.75,-6.7) 22(-4.25,-6.7) 23(-3.75,-6.7) 24(-3.25,-6.7) 25(-2.75,-6.7) 26(-2.25,-6.7) 27(-1.75,-6.7) 28(-1.25,-6.7) 29(-0.75,-6.7) 30(-0.25,-6.7) 31(0.25,-6.7) 32(0.75,-6.7) 33(1.25,-6.7) 34(1.75,-6.7) 35(2.25,-6.7) 36(2.75,-6.7) 37(3.25,-6.7) 38(3.75,-6.7) 39(4.25,-6.7) 40(4.75,-6.7) 61(4.75,6.7) 62(4.25,6.7) 63(3.75,6.7) 64(3.25,6.7) 65(2.75,6.7) 66(2.25,6.7) 67(1.75,6.7) 68(1.25,6.7) 69(0.75,6.7) 70(0.25,6.7) 71(-0.25,6.7) 72(-0.75,6.7) 73(-1.25,6.7) 74(-1.75,6.7) 75(-2.25,6.7) 76(-2.75,6.7) 77(-3.25,6.7) 78(-3.75,6.7) 79(-4.25,6.7) 80(-4.75,6.7)
  rect 4.85x4.85 smd: H(0,0)
MOL_SMA73391007X
  round 2.3 hole 1.55: G1(-2.54,2.54) G2(2.54,2.54) G3(-2.54,-2.54) G4(2.54,-2.54)
  rect 2.3x2.3 hole 1.55: S(0,0)
OSCCC200X250X90-4M
  rect 1.45x1.25 smd: 1(-0.95,-0.8) 2(0.95,-0.8) 3(0.95,0.8) 4(-0.95,0.8)
OST_OSTVN03A150
  rect 1.9x1.9 hole 1.3: 1(0,0)
  round 1.9 hole 1.3: 2(2.54,0) 3(5.08,0)
PULSE_PA4332
  rect 3.7x1.1 smd: 1(0,1.5) 2(0,-1.5)
QFN40P800X800_68-H580N
  rect 0.8x0.2 smd: 1(-3.95,3.2) 2(-3.95,2.8) 3(-3.95,2.4) 4(-3.95,2) 5(-3.95,1.6) 6(-3.95,1.2) 7(-3.95,0.8) 8(-3.95,0.4) 9(-3.95,0) 10(-3.95,-0.4) 11(-3.95,-0.8) 12(-3.95,-1.2) 13(-3.95,-1.6) 14(-3.95,-2) 15(-3.95,-2.4) 16(-3.95,-2.8) 17(-3.95,-3.2) 35(3.95,-3.2) 36(3.95,-2.8) 37(3.95,-2.4) 38(3.95,-2) 39(3.95,-1.6) 40(3.95,-1.2) 41(3.95,-0.8) 42(3.95,-0.4) 43(3.95,0) 44(3.95,0.4) 45(3.95,0.8) 46(3.95,1.2) 47(3.95,1.6) 48(3.95,2) 49(3.95,2.4) 50(3.95,2.8) 51(3.95,3.2)
  rect 0.2x0.8 smd: 18(-3.2,-3.95) 19(-2.8,-3.95) 20(-2.4,-3.95) 21(-2,-3.95) 22(-1.6,-3.95) 23(-1.2,-3.95) 24(-0.8,-3.95) 25(-0.4,-3.95) 26(0,-3.95) 27(0.4,-3.95) 28(0.8,-3.95) 29(1.2,-3.95) 30(1.6,-3.95) 31(2,-3.95) 32(2.4,-3.95) 33(2.8,-3.95) 34(3.2,-3.95) 52(3.2,3.95) 53(2.8,3.95) 54(2.4,3.95) 55(2,3.95) 56(1.6,3.95) 57(1.2,3.95) 58(0.8,3.95) 59(0.4,3.95) 60(0,3.95) 61(-0.4,3.95) 62(-0.8,3.95) 63(-1.2,3.95) 64(-1.6,3.95) 65(-2,3.95) 66(-2.4,3.95) 67(-2.8,3.95) 68(-3.2,3.95)
  rect 5.8x5.8 smd: H(0,0)
QFN50P250X300X100-15M_NOFID
  custom 0.062x0.062 smd: 1(-1.15,0.75) 2(-1.15,0.25) 3(-1.15,-0.25) 4(-1.15,-0.75) 5(-0.75,-1.4) 6(-0.25,-1.4) 8(0.75,-1.4) 12(0.75,1.4) 14(-0.25,1.4) 15(-0.75,1.4)
  custom 0.175x0.175 smd: 7(0.525,-1.4) 13(0.525,1.4)
  custom 0.088x0.088 smd: 9(0.775,-0.5) 10(0.6,0) 11(0.775,0.5)
RESC1005_0402M
  rect 0.56x0.62 smd: 1(-0.54,0) 2(0.54,0)
RESC1005_0402N
  rect 0.4x0.55 smd: 1(-0.425,0) 2(0.425,0)
RESC1608_0603N
  rect 0.9x1 smd: 1(-0.75,0) 2(0.75,0)
RESC2012X60N
  rect 0.95x1.4 smd: 1(-0.95,0) 2(0.95,0)
RTST254P1X08_W265
  rect 1.72x1.72 hole 1.02: 1(0,0)
  round 1.72 hole 1.02: 2(2.54,0) 3(5.08,0) 4(7.62,0) 5(10.16,0) 6(12.7,0) 7(15.24,0) 8(17.78,0)
RTST254P1X08_W265_VER1
  rect 1.7x1.7 hole 1: 1(0,0)
  round 1.7 hole 1: 2(2.54,0) 3(5.08,0) 4(7.62,0) 5(10.16,0) 6(12.7,0) 7(15.24,0) 8(17.78,0)
RTST254P1X10_W265
  rect 1.72x1.72 hole 1.02: 1(0,0)
  round 1.72 hole 1.02: 2(2.54,0) 3(5.08,0) 4(7.62,0) 5(10.16,0) 6(12.7,0) 7(15.24,0) 8(17.78,0) 9(20.32,0) 10(22.86,0)
SODFL1608X77M
  rect 0.61x0.787 smd: A(-0.838,0) K(0.838,0)
SOIC127P800X216-8N
  rect 1.5x0.6 smd: 1(-3.65,1.905) 2(-3.65,0.635) 3(-3.65,-0.635) 4(-3.65,-1.905) 5(3.65,-1.905) 6(3.65,-0.635) 7(3.65,0.635) 8(3.65,1.905)
SON65P300X300X110-8N_TP
  rect 0.9x0.3 smd: 1(-1.5,0.975) 2(-1.5,0.325) 3(-1.5,-0.325) 4(-1.5,-0.975) 5(1.5,-0.975) 6(1.5,-0.325) 7(1.5,0.325) 8(1.5,0.975)
  rect 1.6x2.4 smd: H(0,0)
SOT23_G_S_D-DIODES
  rect 0.8x0.899 smd: D(0,1) G(-0.95,-1) S(0.95,-1)
SOT95P230X110-3N
  rect 0.5x0.8 smd: D(0,1) G(-0.95,-1) S(0.95,-1)
SOT323_SC70-3N_NXP
  rect 0.6x0.7 smd: D(0,1.05) G(-0.65,-1.05) S(0.65,-1.05)
SOT666_6N-NXP
  rect 0.375x0.5 smd: 1(-0.537,-0.85) 3(0.537,-0.85) 4(0.537,0.85) 6(-0.537,0.85)
  rect 0.3x0.65 smd: 2(0,-0.925) 5(0,0.925)
SOTFL40P120X59-3N
  rect 0.45x0.4 smd: 1(-0.525,0.4) 2(-0.525,-0.4) 3(0.525,0)
SULLINS_PPPC091LFBN-RC_VER1
  rect 1.7x1.7 hole 1: 1(0,0)
  round 1.7 hole 1: 2(2.54,0) 3(5.08,0) 4(7.62,0) 5(10.16,0) 6(12.7,0) 7(15.24,0) 8(17.78,0) 9(20.32,0)
SW_EVQ-PE105K
  rect 2x1.6 smd: A(-2.7,0) B(2.7,0)
SW_SKRPACE010
  rect 1.05x0.65 smd: 1(-2.075,1.075) 2(2.075,1.075) 3(-2.075,-1.075) 4(2.075,-1.075)
TDFN50P160X120_4-HS86X50M
  rect 0.7x0.3 smd: 1(-0.8,0.25) 2(-0.8,-0.25) 3(0.8,-0.25) 4(0.8,0.25)
  rect 0.5x0.86 smd: H(0,0)
TO254P1524X483-4N_TI
  rect 2.16x1.07 smd: 1(-6.545,2.54) 2(-6.545,0) 3(-6.545,-2.54)
  rect 6.99x10.8 smd: H(4.13,0)
TP102C
  round 1.016 smd: 1(0,0)
TPT_KEY_5000
  round 1.72 hole 1.02: 1(0,0)
TRIM_3386P-1-103TLF
  rect 1.36x1.36 hole 0.76: 1(0,0)
  round 1.36 hole 0.76: 2(2.54,-2.54) 3(5.08,0)
unnamed#2
  round 1 smd: (0,0)
WURTH_61304021821
  rect 1.62x1.62 hole 1.02: 1(0,0)
  round 1.62 hole 1.02: 2(0,2.54) 3(2.54,0) 4(2.54,2.54) 5(5.08,0) 6(5.08,2.54) 7(7.62,0) 8(7.62,2.54) 9(10.16,0) 10(10.16,2.54) 11(12.7,0) 12(12.7,2.54) 13(15.24,0) 14(15.24,2.54) 15(17.78,0) 16(17.78,2.54) 17(20.32,0) 18(20.32,2.54) 19(22.86,0) 20(22.86,2.54) 21(25.4,0) 22(25.4,2.54) 23(27.94,0) 24(27.94,2.54) 25(30.48,0) 26(30.48,2.54) 27(33.02,0) 28(33.02,2.54) 29(35.56,0) 30(35.56,2.54) 31(38.1,0) 32(38.1,2.54) 33(40.64,0) 34(40.64,2.54) 35(43.18,0) 36(43.18,2.54) 37(45.72,0) 38(45.72,2.54) 39(48.26,0) 40(48.26,2.54)
XTAL_ABS05_1M6X1M
  rect 0.5x1 smd: 1(-0.6,0) 2(0.6,0)

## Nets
GND_EARTH: C79.1 J15.SH1 J15.SH2 J15.SH3 J15.SH4 JMP1.1 JMP1.2 R115.2
GND_SIGNAL: C1.1 C2.2 C3.2 C4.2 C5.2 C6.2 C7.1 C8.2 C9.2 C10.1 C11.2 C12.2 C13.2 C14.1 C15.2 C16.1 C17.2 C18.2 C19.1 C20.2 C21.2 C22.1 C23.2 C24.1 C25.1 C26.1 C27.2 C28.2 C29.1 C30.2 C31.1 C32.1 C33.1 C34.1 C35.1 C36.1 C37.2 C38.1 C39.1 C40.1 C41.1 C42.2 C43.2 C44.2 C45.2 C46.2 C47.2 C48.2 C49.2 C50.2 C51.2 C52.2 C53.2 C54.2 C55.2 C56.2 C57.2 C58.2 C59.2 C60.2 C61.2 C62.2 C63.2 C65.2 C66.1 C67.2 C79.2 C80.2 C81.2 C82.2 C83.2 C84.2 C85.2 C86.2 C87.2 C88.2 C90.2 C92.2 C93.2 C95.2 C96.2 C97.2 C98.2 D1.A D2.A D3.A D6.2 J1.2 J1.3 J3.7 J5.1 J5.40 J7.G1 J7.G2 J7.G3 J7.G4 J8.6 J10.3 J11.3 J11.5 J11.7 J11.9 J12.8 J13.G1 J13.G2 J13.G3 J13.G4 J14.3 J14.5 J14.9 J14.15 J14.17 J14.19 J15.A1 J15.A12 J15.B1 J15.B12 J16.8 J20.2 J20.3(SWITCH) J21.6 J23.3 J24.1 J24.40 J25.2 LED3.K(CATHODE) Q2.G Q10.S R1.1 R62.1 R67.1 R80.2 R81.1 R83.2 R98.1 R99.2 R115.1 R117.2 R125.1 R127.2 R129.2 R130.2 R132.2 R133.1 R134.1 R135.1 R138.2 R139.2 R140.2 R142.1 R146.2 R150.1 R154.2 R155.1 SW1.B(2) SW2.A SW3.3 SW3.4 SW4.B(2) TP1.1(TP) TP6.1(TP) TP8.1(TP) TP13.1(TP) U1.6 U1.7 U1.77 U1.78 U1.H U2.5 U2.7 U2.8 U2.9 U2.25 U2.43 U2.45 U2.58 U2.62 U2.63 U2.H U3.4 U4.2 U4.H U5.2 U5.H(PAD) U7.3 U8.4 U8.6 U8.10 U8.15(VSEL) U9.2 U9.H Y1.2 Y1.4(GND#4)
VCC_FLASH: C66.2 R107.1 U3.8
VCC_IN: C80.1 C81.1 C82.1 C84.1 D4.K D5.K R121.2 R124.1 TP9.1(TP) U8.12 U8.13
VCC_IO_CAN: C40.2 R131.1 U4.5(VIO)
VCCD: C11.1 U1.10
VDD_POT: J9.2 R1.3 R49.2
VDDA: C30.1 C63.1 FB2.2 J9.1 R49.1 R80.1 R93.1 U1.66
VDDD: C18.1 C54.1 FB1.2 R44.1 R109.1 U1.9
VDDIO_0: C2.1 C9.1 C44.1 C45.1 C46.1 C51.1 R55.1 U1.20 U1.40 U1.49
VDDIO_1: C27.1 C59.1 R78.1 U1.80
VIN: C92.1 D5.A D6.1 J20.1 R42.1 R132.1
VIN_EXP: J1.1 J5.39 J24.2 R42.2
AN_A0: C14.2 R68.1 U1.53
AN_A1: C19.2 R70.1 U1.54
AN_A2: C22.2 R71.1 U1.55
AN_A3: C24.2 R74.1 U1.56
AN_A4: C26.2 R77.1 U1.57
AN_A5: C29.2 R82.1 U1.58
AN_A6: C38.2 R85.1 U1.59
AN_A7: C39.2 R97.1 U1.60
AN_B2: C31.2 R94.1 U1.63
AN_B3: C32.2 R91.1 U1.64
AN_B4: C33.2 R90.1 U1.67
AN_B5: C34.2 R89.1 U1.68
AN_B6: C35.2 R88.1 U1.69
AN_B7: C36.2 R87.1 U1.70
ARD_A0: J2.1 J24.23 R68.2
ARD_A1: J2.2 J24.25 R70.2
ARD_A2: J2.3 J24.27 R71.2
ARD_A3: J2.4 J24.22 R74.2
ARD_A4: J2.5 J8.2 J16.1 J21.2 J24.24 R77.2
ARD_A5: J2.6 J8.3 J21.3 J24.26 R82.2
ARD_A6: J2.7 J24.34 R85.2
ARD_A7: J24.20 R97.2
ARD_B0: R33.2 R36.1 U1.61
ARD_B0_EXP: J24.16 R33.1
ARD_B1: R6.1 R7.2 U1.62
ARD_B1_EXP: J24.18 R7.1
ARD_B2: J24.17 R94.2
ARD_B3: J24.19 R91.2
ARD_B5: J24.28 R89.2
ARD_B6: J24.30 R88.2
ARD_B7: J2.8 J24.32 R87.2
CAN_RX1: R136.1 R137.2 U1.37
CAN_STB: R151.2 U4.8
CAN_TX1: R148.1 R149.2 U1.38
CS: R20.2 R41.2 R113.2 R114.1 U1.71
DFU_SW1: J19.2 J24.10 U1.21
DFU_SW2: J22.2 J24.9 U1.22
ECO_IN: R17.1 R18.2 U1.14
ECO_OUT: R13.2 R14.1 U1.15
ETM_TRACE_CLK: J14.12 R24.1
ETM_TRACE_D0: J14.14 R20.1
ETM_TRACE_D1: J14.16 R16.1
ETM_TRACE_D2: J14.18 R12.1
ETM_TRACE_D3: J14.20 R10.1
EXT_CLK: R27.2 TP4.1(TP)
HDR_3V3: J1.5 J5.2 J8.7 J16.7 J21.7 J24.39 Q5.S Q7.4(E) R141.2
HDR_5V0: J1.4 J8.1 J12.7 J21.1 Q4.S Q6.4(E) R143.2
HDR_I2C_SCL: J3.10 J5.21 J8.5 J12.5 J21.5 R47.2
HDR_I2C_SDA: J3.9 J5.23 J8.4 J12.6 J21.4 R48.2
I2C_SCL: R47.1 R50.1 R53.2 U1.79
I2C_SDA: R48.1 R51.1 R54.2 U1.2
KP_I2C_SCL: R53.1 U2.38
KP_I2C_SDA: R54.1 U2.39
KP_RESET: R25.2 U2.3
KP_SWCLK: R37.1 U2.47
KP_SWDIO: R39.1 U2.46
KP_USB_DM: J15.A7 J15.B7 R72.1 U7.1
KP_USB_DP: J15.A6 J15.B6 R75.1 U7.2(IN2)
KP_VBUS: D4.A Q3.D R102.2 R108.2 R117.1
KP_VBUS_IN: C65.1 D3.K(CATHODE) J15.A4 J15.A9 J15.B4 J15.B9(VBUS_4) Q2.D R102.1 TP7.1(TP)
LPCOMP0_INN: J5.13 R95.1
LPCOMP0_INP: J5.19 R113.1
LPCOMP1_INN: J5.17 R100.1
LPCOMP1_INP: J5.15 R104.1
MISO: R12.2 R104.2 R105.1 U1.73
MOSI: R16.2 R95.2 R96.1 U1.72
P0_1: J5.5 R21.2
P1_0: J24.37 R17.2
P1_1: J5.7 R13.1
P2_0: R28.2 R29.2 R158.2 U1.18
P2_1: R30.2 R31.2 U1.19
P3_0: J4.8 J5.24 U1.23
P3_1: J5.28 J6.4 J18.4 U1.24
P3_VDD: FB1.1 FB2.1 J17.1 R55.2 R69.2 R78.2 R157.2
P4_4: R23.2 U1.31
P4_4_EXP: J5.36 R23.1
P4_5: J5.37 J8.8 J21.8 U1.32
P5_0: J24.36 R160.2 U1.35
P5_2: J24.35 R136.2
P5_3: J24.33 R148.2
P5LP1_2: SW3.1 SW3.2 U2.13
P5LP1_4: R106.2 U2.15
P5LP2_2: U2.64
P5LP2_3: U2.65
P5LP2_4: U2.66
P5LP_SIO_VREF: R61.2 R62.2 U2.48
P5LP_SWCLK: J25.4 U2.12
P5LP_SWDIO: J25.5 U2.11
P5LP_VCCD: C15.1 C17.1 U2.26 U2.57
P5LP_VDD: C4.1 C6.1 C8.1 C20.1 C21.1 C23.1 C28.1 C47.1 C48.1 C49.1 C55.1 C56.1 C57.1 C60.1 J25.1 R79.1 R108.1 U2.17 U2.24 U2.35 U2.44 U2.52 U2.59 U2.67
P5LP_XRES: J25.3 U2.10(X\R\E\S\)
P7_4: R24.2 R159.2 U1.48
P7_6: J3.1 J5.22 R151.1 U1.51
P7_7: J12.2 J24.4 U1.52
P8_4: J24.6 R46.2 U1.75
P8_5: J24.8 R45.2 U1.76
P9_4: J5.11 J6.5 J18.5 R76.2 U1.4
P9_5: J5.9 J16.3 R73.2 U1.5
PERI_HRPWM_0: R32.2 R34.2 R35.2 R159.1
PERI_HRPWM_0_EXP: J5.4 R34.1
PERI_HRPWM_1: R4.2 R5.2 R8.2 U1.50
PERI_HRPWM_1_EXP: J5.6 R8.1
PERI_HRPWM_2: J5.8 U1.33
PERI_HRPWM_3: J5.10 U1.34
POT: R2.2 R3.2 R90.2
POT_EXP: J24.21 R3.1
PWM_SHIELD: J8.9 J12.1 J21.9 J24.12 U1.36
SPI_CLK_ARD: J3.6 J5.18 J6.6 J16.4 J18.6 U1.44
SPI_CLK_FLASH: R101.2 U3.6
SPI_CLK_MCU: R10.2 R100.2 R101.1 U1.74
SPI_CS01_ARD: J3.3 J5.16 U1.47
SPI_CS_FLASH: R114.2 U3.1
SPI_MISO_ARD: J3.5 J5.20 J6.8 J16.5 J18.8 U1.46
SPI_MISO_FLASH: R105.2 U3.2
SPI_MOSI_ARD: J3.4 J5.14 J6.7 J16.6 J18.7 U1.45
SPI_MOSI_FLASH: R96.2 U3.5
TCLK_SWCLK: J11.4 J14.4 R38.1 R59.1
TCLK_SWCLK_MCU: R37.2 R38.2 U1.16
TCPWM1_COMPL_EXP: J4.6 J5.34 R15.1
TCPWM1_COMPL_EXP_MCU: R15.2 U1.28
TCPWM1_EXP: J4.4 J5.35 R19.1
TCPWM1_EXP_MCU: R19.2 U1.27
TCPWM2_COMPL_EXP_MCU: J24.3 U1.3
TCPWM2_EXP_MCU: J5.25 U1.1
TCPWM_518: J24.14 R28.1
TCPWM_518_COMPL: J24.11 R30.1
TCPWM_COMPL_EXP: J3.2 J5.32 R9.1
TCPWM_COMPL_EXP_MCU: R9.2 U1.30
TCPWM_EXP: J4.7 J5.33 R11.1
TCPWM_EXP_MCU: R11.2 U1.29
TDI: J11.8 J14.8 R29.1 R52.1
TDO: J11.6 J14.6 R31.1
TMS_SWDIO: J11.2 J14.2 R40.1 R60.1
TMS_SWDIO_MCU: R39.2 R40.2 U1.17
UART_1_RX: R63.1 U2.21
UART_1_RX_EXP: J24.7 R58.1
UART_1_TX: R56.1 U2.20
UART_1_TX_EXP: J24.5 R65.1
UART_CTS_1: J4.5 J24.29 U1.39
UART_RTS_1: J4.3 J24.31 U1.41
UART_RX: J10.2 R56.2 R57.1 R58.2 U1.42
UART_RX_0_MIK: J4.1 J5.31 J6.1 J12.3 J18.1 U1.25
UART_TX: J10.1 R63.2 R64.1 R65.2 U1.43
UART_TX_0_MIK: J4.2 J5.29 J6.2 J12.4 J18.2 U1.26
USB_V_SENSE: R79.2 R81.2 U2.19
USER_SWITCH: C43.1 R44.2 R158.1 SW2.B(2)
VAREF_EXT: C37.1 R92.2 R93.2 U1.65
VBACKUP: C50.1 C53.1 R69.1 U1.11
VOUT_3V3: C61.1 C97.1 C98.1 J17.2 Q5.D Q7.1 R116.1 R141.1 R156.2 TP10.1(TP) U5.1 U9.3(OUT)
VOUT_5V0: C41.2 C83.1 C85.1 C86.1 C87.1 C88.1 C91.1 C95.1 C96.1 Q4.D Q6.1 R123.1 R126.1 R143.1 TP12.1(TP) U4.3 U8.7 U8.8 U9.1
VREFH: J3.8 J24.15 R92.1
VTARG_DEBUG: C52.1 D1.K(CATHODE) J11.1 J14.1 Q8.S Q9.4(E) R52.2 R59.2 R60.2 R147.2
VTARG_MEAS: R66.2 R67.2 U2.32
VTARG_REF: C58.1 J1.7 LED1.A LED2.A Q8.D Q9.1 Q10.G R41.1 R43.1 R50.2 R51.2 R57.2 R61.1 R64.2 R66.1 R73.1 R76.1 R107.2 R128.1 R131.2 R147.1 R150.2 R153.1 U5.4
VTARG_REF_EN: R86.2 R156.1 R157.1
WCO_IN: R21.1 R22.1 U1.13
WCO_OUT: R26.1 R27.1 U1.12
XRES_L_MCU: C67.1 J1.6 J5.30 J6.3 J11.10 J14.10 J16.2 J18.3 R25.1 R109.2 SW1.A U1.8(XRES)
N22087450: C12.1 U2.53
N22087778: C5.1 U2.42
N22087991: R75.2 U2.22
N22087993: R72.2 U2.23
N22088003: C13.1 U2.31
N22088231: LED3.A R106.1
N22092982: Q8.G Q9.3 R146.1
N22093014: Q9.2 Q9.5 R142.2
N22093052: Q9.6 R138.1
N22129895: C10.2 R22.2 Y2.2
N22129929: C7.2 R18.1 Y1.3
N22129931: C3.1 R14.2 Y1.1
N22129945: C16.2 R26.2 Y2.1
N22154314: J15.A5 R99.1
N22154327: J15.B5 R83.1
N22156925: L1.1 U8.11
N22156929: L1.2 U8.9
N22157101: R121.1 U8.14
N22157103: R126.2 TP11.1(TP) U8.2
N22157131: R124.2 R125.2 U8.1
N22157141: C90.1 U8.3
N22157156: C91.2 R123.2 R134.2 U8.5
N22173555: C25.2 R35.1 R36.2 TP5.1(TP)
N22173666: C1.2 R5.1 R6.2 TP3.1(TP)
N22184104: Q4.G Q6.3 R139.1
N22184124: Q5.G Q7.3 R140.1
N22184135: Q6.2 Q6.5 R133.2
N22184141: Q7.2 Q7.5 R135.2
N22184147: Q6.6 R127.1
N22184151: Q7.6 R130.1
N22185312: C42.1 R1.2(WIPER) R2.1
N22190096: J24.38 R43.2 R160.1 SW4.A
N22190335: LED2.K(CATHODE) R46.1
N22190371: LED1.K(CATHODE) R45.1
N22190519: J19.1 R128.2
N22190521: J22.1 R153.2
N22190557: J19.3 R129.1
N22190561: J22.3 R154.1
N22191822: C62.1 R86.1 R155.2 U5.3
N22248472: J13.S(RF_IN) R32.1
N22248626: J7.S(RF_IN) R4.1
N22257092: C94.2 J23.1 R144.1 R152.1 U4.6
N22257130: C94.1 J23.2 R145.2 R152.2 U4.7
N22257140: C93.1 R144.2 R145.1
N22258155: R149.1 U4.1
N22258259: R137.1 U4.4
N22258799: Q1.S Q2.S Q3.S R84.2
N22258824: Q1.D Q3.G R98.2
N22258828: D2.K(CATHODE) Q1.G R84.1
N22307724: LED4.K(CATHODE) Q10.D
N223077121: LED4.A R116.2

Pads without a net: J1 8; J5 3 12 26 27 38; J14 7 11 13; J15 A8 B8; J24 13; U2 1 2 4 6 14 16 18 27 28 29 30 33 34 36 37 40 41 49 50 51 54 55 56 60 61 68; U3 3 7

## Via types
v1: diameter 0.45, hole 0.2, TOP to BOTTOM, 611 vias
v2: diameter 0.5, hole 0.25, TOP to BOTTOM, 35 vias

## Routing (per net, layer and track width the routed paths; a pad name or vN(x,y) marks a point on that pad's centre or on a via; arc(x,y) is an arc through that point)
GND_EARTH: length 25.1
  BOTTOM w0.381: JMP1.2 126.11,36.35 ; JMP1.2 125.03,37.42 ; JMP1.2 125.03,35.27 ; JMP1.2 123.95,36.35 ; J15.SH2 123.22,34.88 ; J15.SH2 123.22,33.45 ; J15.SH2 121.95,34.17 ; J15.SH2 124.49,34.17 ; 122.8,20.98 C79.1 122.3,21.51 ; JMP1.1 125.03,24.42 ; JMP1.1 126.11,23.35 ; JMP1.1 123.95,23.35 ; JMP1.1 125.03,22.27 ; R115.2 122.24,22.74 ; R115.2 122.66,22.25 ; R115.2 122.24,21.76 ; 127.4,24.81 J15.SH3 ; J15.SH3 127.4,26.24 ; J15.SH3 126.28,25.53 ; J15.SH3 128.52,25.53 ; 127.4,33.45 J15.SH4 ; J15.SH4 126.28,34.17 ; J15.SH4 127.4,34.88 ; J15.SH4 128.52,34.17 ; J15.SH1 124.49,25.53 ; J15.SH1 123.22,26.24 ; J15.SH1 123.22,24.81
GND_SIGNAL: length 1026.5
  TOP w0.191: v1(87.78,40.54) 87.49,40.83 U2.45 ; v1(85.75,36.47) 85.75,36.68 85.56,36.87 U2.63 ; U2.7 87.49,35.27 87.68,35.46 v1(87.78,35.46) 87.89,35.35 U2.8 ; U2.9 88.29,35.28 88.48,35.47 88.79,35.47 v1(88.8,35.46) ; v1(90.83,37.49) 91.01,37.67 U2.25 ; v1(86.77,35.46) 86.69,35.38 U2.5 ; U2.43 88.29,40.6 88.35,40.54 v1(88.8,40.54) ; U2.58 85.56,38.87 85.75,38.68 v1(85.75,38.51) ; v1(85.75,37.49) 85.53,37.27 U2.62
  TOP w0.229: 69.13,39.4 68.96,39.58 U1.7
  TOP w0.254: U1.6 69.05,39.08
  TOP w0.292: U1.7 66.77,39.58 v1(66.73,39.62) ; U1.77 64.64,33.71 v1(64.92,33.43) 65.14,33.65 U1.78 ; 66.75,39.04 66.79,39.08 U1.6
  TOP w0.305: v1(37.47,13.74) 37.77,13.43 U4.2
  TOP w0.381: J12.8 25.84,46.23 ; J12.8 23.69,46.23 ; J12.8 24.77,45.15 ; J12.8 24.77,47.31 ; 41.26,4.37 TP13.1 ; TP13.1 43.42,4.37 ; TP13.1 42.34,5.45 ; TP13.1 42.34,3.29 ; 62.3,30.03 C34.1 ; C34.1 63.74,30.03 ; C34.1 63.02,29.36 ; C34.1 63.02,30.69 ; U3.4 84.02,29.16 ; U3.4 82.08,29.16 ; U3.4 83.05,28.64 ; U3.4 83.05,29.68 ; C97.2 76.03,21.6 ; C97.2 75.31,20.93 ; C97.2 74.59,21.6 ; 70.89,37.91 C18.2 70.36,38.41 ; C95.2 74.68,19.9 ; C95.2 75.2,19.4 ; C95.2 74.15,19.4 ; 54.36,29.19 C31.1 ; C31.1 54.36,30.53 ; C31.1 53.64,29.86 ; SW4.B 45.86,67.01 ; SW4.B 47.08,65.99 ; SW4.B 45.86,64.97 ; 75.74,45.63 Y1.2 75.81,46.9 ; 32.54,59.87 J7.G3 ; J7.G3 33.91,61.24 ; J7.G3 32.54,62.61 ; J7.G3 31.17,61.24 ; C36.1 66.7,30.69 ; C36.1 65.98,30.03 ; C36.1 66.7,29.36 ; C36.1 67.42,30.03 ; 76.95,49.89 C3.2 ; C3.2 77.68,49.87 ; C3.2 77.7,49.14 ; 15.88,53.29 J8.6 ; J8.6 14.81,54.36 ; J8.6 15.88,55.42 ; J8.6 16.94,54.36 ; C5.2 89.68,44.93 ; C5.2 v1(89.15,45.72) ; C5.2 88.63,44.93 ; 117.6,12.19 J20.3 ; J20.3 119.09,13.31 ; J20.3 120.58,12.19 ; J20.3 119.09,11.07 ; 37.62,45.52 J13.G2 ; J13.G2 36.25,46.89 ; J13.G2 38.99,46.89 ; J13.G2 37.62,48.26 ; C1.1 35.92,50.96 ; C1.1 35.2,51.63 ; C1.1 34.49,50.96 ; 49.45,39.75 C14.1 48.78,39.03 ; 71.2,41.15 C11.2 72.54,41.15 ; J21.6 15.88,6.15 ; J21.6 14.81,5.08 ; J21.6 16.94,5.08 ; J21.6 15.88,4.01 ; 36.25,41.81 J13.G4 ; J13.G4 38.99,41.81 ; J13.G4 37.62,40.44 ; J13.G4 37.62,43.18 ; 76.57,43 C7.1 77.32,43.75 ; 50.1,57.81 SW2.A ; SW2.A 51.32,56.79 ; SW2.A 51.32,58.83 ; 121.02,7.37 J20.2 ; J20.2 123.26,7.37 ; J20.2 122.14,5.88 ; J20.2 122.14,8.85 ; 91.04,44.93 C6.2 ; C6.2 91.57,45.43 ; C6.2 92.3,44.93 v1(92.35,44.98) ; 81.18,40.19 C12.2 ; C12.2 v1(80.37,40.72) ; C12.2 81.18,41.24 ; 36.96,12.34 U4.H 36.96,15.18 ; 32.54,40.44 J13.G3 ; J13.G3 31.17,41.81 ; J13.G3 32.54,43.18 ; J13.G3 33.91,41.81 ; U9.2 70.55,22.6 ; U9.2 71.85,21.84 ; U9.2 69.25,21.84 ; U9.2 70.55,21.09 ; 95.25,39.76 C13.2 ; C13.2 95.25,40.89 v1(95.4,41.05) ; C13.2 95.75,40.28 ; J23.3 37.21,5.54 ; J23.3 36.04,4.37 ; J23.3 37.21,3.2 ; J23.3 38.38,4.37 ; C26.1 48.78,32.85 ; C26.1 48.78,31.41 ; C26.1 49.45,32.13 ; 109.83,29.25 SW3.3 ; SW3.3 111.32,29.25 ; SW3.3 110.57,29.8 ; TP8.1 100.06,29.11 ; TP8.1 97.91,29.11 ; TP8.1 98.98,30.19 ; TP8.1 98.98,28.03 ; 81.18,34.52 C23.2 ; C23.2 v1(81.18,35.92) ; C23.2 80.68,35.05 ; 95.25,36.94 C21.2 95.25,38.2 v1(95.15,38.3) ; 114.68,45.64 J25.2 ; J25.2 115.65,46.61 ; J25.2 113.71,46.61 ; J25.2 114.68,47.58 ; 84.33,9.72 J1.2 84.33,11.87 ; 36.58,32.31 C25.1 ; C25.1 36.58,33.65 ; C25.1 35.86,32.98 ; C25.1 37.29,32.98 ; J5.1 110.25,67.31 ; J5.1 108.19,67.31 ; J5.1 109.22,66.28 ; J5.1 109.22,68.34 ; C22.1 49.45,35.94 ; C22.1 48.78,35.22 ; C22.1 48.78,36.66 ; J7.G1 32.54,67.69 ; J7.G1 33.91,66.32 ; J7.G1 31.17,66.32 ; J7.G1 32.54,64.95 ; 121.85,33.2 J15.A12 ; C33.1 61.11,30.69 ; C33.1 61.11,29.36 ; C33.1 60.39,30.03 ; C33.1 61.83,30.03 ; TP1.1 55.71,61.75 ; TP1.1 54.64,62.83 ; TP1.1 53.56,61.75 ; TP1.1 54.64,60.67 ; C20.2 v1(81.18,37.16) ; C20.2 80.68,37.97 ; C20.2 81.18,38.5 ; 32.79,14.46 C40.1 ; C40.1 v1(32.79,15.77) ; C40.1 32.3,14.99 ; C32.1 55.88,30.53 ; C32.1 55.88,29.19 ; C32.1 56.6,29.86 ; 61.39,38.68 U1.H ; U1.H 61.39,43.97 ; U1.H 58.75,41.33 ; U1.H 64.04,41.33 ; 47.88,50.85 J10.3 ; J10.3 49.81,50.85 ; J10.3 48.84,51.82 ; J10.3 48.84,49.88 ; J16.8 24.77,24.45 ; J16.8 24.77,22.29 ; J16.8 23.69,23.37 ; J16.8 25.84,23.37 ; 48.78,27.6 C38.1 ; C38.1 49.45,28.32 ; C38.1 48.78,29.04 ; C28.2 92.83,32.68 ; C28.2 93.33,32.16 ; C28.2 v1(92.83,31.42) ; J24.40 110.25,5.08 ; J24.40 109.22,4.05 ; J24.40 109.22,6.11 ; J24.40 108.19,5.08 ; C27.2 69.21,33.07 ; C27.2 69.71,32.54 ; C27.2 69.21,32.01 ; J3.7 67.56,60.13 ; J3.7 68.64,59.05 ; J3.7 67.56,57.98 ; C30.2 60.22,30.51 ; C30.2 59.69,28.96 v1(59.21,28.47) ; C30.2 59.16,30.51 ; SW1.B 39.23,25.45 ; SW1.B 39.23,23.42 ; SW1.B 38.01,24.43 ; C37.2 58.77,30.48 ; C37.2 57.71,30.48 ; C37.2 58.24,29.98 ; 51.29,41.18 C9.2 ; C9.2 51.82,40.64 ; C9.2 52.34,41.18 ; 80.68,42.04 C8.2 ; C8.2 v1(81.18,42.83) ; C8.2 81.18,41.51 ; 87.23,44.93 C4.2 ; C4.2 87.76,45.72 v1(88.04,46) ; C4.2 88.29,44.93 ; J14.5 109.57,41.15 ; 72.46,21.33 C98.2 ; C98.2 73.41,22.12 ; C98.2 74.35,21.33 ; C98.2 73.41,20.53 ; 36.25,61.24 J7.G4 ; J7.G4 38.99,61.24 ; J7.G4 37.62,62.61 ; J7.G4 37.62,59.87 ; 37.62,64.95 J7.G2 ; J7.G2 36.25,66.32 ; J7.G2 38.99,66.32 ; J7.G2 37.62,67.69 ; 126.36,50 J11.9 124.95,49.4 ; 73.68,19.4 C96.2 73.15,19.9 ; 76.48,38.69 C16.1 ; C16.1 v1(77.95,38.69) ; C16.1 77.01,38.19 ; 120.62,62.84 R1.1 ; R1.1 120.62,64.64 ; R1.1 121.52,63.74 ; R1.1 119.72,63.74 ; 48.78,37.13 C19.1 ; C19.1 48.78,38.56 ; C19.1 49.45,37.85 ; 121.85,26.8 J15.B12 ; 109.57,50.04 J14.19 108.33,50.78 ; C15.2 81.18,39.77 ; C15.2 81.18,38.71 ; C15.2 v1(80.34,39.24) ; J14.9 109.57,43.69 ; C41.1 41.25,13.31 v1(41.17,13.23) ; C29.1 48.78,30.94 ; C29.1 48.78,29.51 ; C29.1 49.45,30.23 ; 124.95,46.86 J11.5 ; TP6.1 118.25,32.72 ; TP6.1 116.8,32.72 ; TP6.1 117.53,31.99 ; LED3.K 112.59,27.64 ; LED3.K 113.31,26.72 ; LED3.K 112.59,25.8 ; LED3.K 111.87,26.72 ; J14.17 109.57,48.77 ; 124.95,48.13 J11.7 ; 49.45,26.42 C39.1 48.78,27.13 ; 124.95,45.59 J11.3 ; 95.25,38.49 C17.2 ; C17.2 95.25,39.54 ; C17.2 v1(95.91,39.01) ; 79.55,47.18 Y1.4 79.48,45.92 ; 57.14,50.12 C2.2 56.64,50.88 v1(56.44,51.08) ; J5.40 60.96,65.8 ; J5.40 60.96,63.74 ; J5.40 59.93,64.77 ; J14.3 109.57,39.88 ; 121.85,26.5 J15.A1 ; 113.98,29.25 SW3.4 ; SW3.4 114.72,29.8 ; SW3.4 115.47,29.25 ; C35.1 65.64,30.03 ; C35.1 64.92,29.36 ; C35.1 64.2,30.03 ; C35.1 64.92,30.69 ; J24.1 61.99,2.54 ; J24.1 59.93,2.54 ; J24.1 60.96,1.51 ; J13.G1 33.91,46.89 ; J13.G1 32.54,45.52 ; J13.G1 31.17,46.89 ; J13.G1 32.54,48.26 ; 77.01,42.3 C10.1 77.62,41.81 v1(77.75,41.68) ; 58.19,29.88 v1(58.19,28.47) ; C24.1 48.78,34.75 ; C24.1 48.78,33.32 ; C24.1 49.45,34.04 ; J14.15 109.57,47.5
  TOP w0.508: Y1.2 v1(75,46.3) ; 71.93,38.86 71.87,38.92 v1(71.87,40.16) C11.2 ; 71.93,38.86 72.67,38.13 74.9,38.13 75.29,37.74 75.29,34.77 75.21,34.7 76.23,33.68 77.67,33.68 78.46,34.47 78.46,38.18 v1(77.95,38.69) 79.25,38.69 79.71,39.14 79.71,41.4 79.2,41.91 77.97,41.91 v1(77.75,41.68) 77.75,42.57 v1(77.62,42.7) ; 71.93,38.86 71.48,38.41 C18.2 ; C39.1 v1(47.93,26.42) ; C14.1 v1(47.9,39.75) ; SW2.A v1(52.98,57.81) ; C26.1 v1(47.88,32.13) ; J11.9 v1(128.15,49.4) ; C29.1 v1(47.88,30.23) ; v1(76.61,50.19) 77.04,50.62 78.08,50.62 80.29,48.41 v1(80.29,46.51) ; v1(76.61,50.19) 77.28,49.51 C3.2 ; v1(76.61,50.19) 74.6,48.18 72.26,48.18 v1(71.53,48.92) 71.15,49.3 70.28,49.3 69.78,48.79 v1(69.78,48.52) 69.78,47.7 68.83,46.76 v1(68.25,46.76) ; C22.1 v1(47.85,35.94) ; SW3.3 v1(110.57,28.28) ; SW4.B 44.27,65.99 v1(44.22,65.94) ; J11.7 v1(128.15,48.13) ; Y1.4 v1(80.29,46.51) ; v1(80.29,46.51) 80.29,45.24 77.75,42.7 v1(77.62,42.7) ; C7.1 v1(77.62,42.7) ; TP6.1 v1(117.53,33.68) ; J11.5 v1(128.15,46.86) ; C24.1 48.51,34.04 v1(48.39,33.91) ; C38.1 v1(47.93,28.32) ; SW3.4 v1(114.72,28.33) ; C19.1 v1(47.88,37.85) ; J11.3 v1(128.15,45.59)
  TOP w0.762: 59.88,21.5 63.96,17.42 ; 59.88,21.5 U9.H ; 59.88,21.5 59.88,21.47 55.73,17.32 ; SW1.B v1(41.15,24.43) ; U9.H 63.59,21.84 ; U9.H 59.88,27.46 ; U9.H 56.16,21.84
  L02_GND w0.381: 109.57,50.04 J14.19 108.33,50.78 ; 41.26,4.37 TP13.1 ; TP13.1 43.42,4.37 ; TP13.1 42.34,5.45 ; TP13.1 42.34,3.29 ; R1.1 120.62,64.64 ; R1.1 121.52,63.74 ; R1.1 119.72,63.74 ; R1.1 120.62,62.84 ; J12.8 25.84,46.23 ; J12.8 24.77,45.15 ; J12.8 24.77,47.31 ; J12.8 23.69,46.23 ; TP1.1 54.64,62.83 ; TP1.1 53.56,61.75 ; TP1.1 54.64,60.67 ; TP1.1 55.71,61.75 ; 37.21,3.2 J23.3 ; J23.3 37.21,5.54 ; J23.3 38.38,4.37 ; J23.3 36.04,4.37 ; 32.54,64.95 J7.G1 ; J7.G1 33.91,66.32 ; J7.G1 32.54,67.69 ; J7.G1 31.17,66.32 ; 97.91,29.11 TP8.1 ; TP8.1 98.98,30.19 ; TP8.1 98.98,28.03 ; TP8.1 100.06,29.11 ; 108.19,67.31 J5.1 ; J5.1 109.22,66.28 ; J5.1 110.25,67.31 ; J5.1 109.22,68.34 ; J14.5 109.57,41.15 ; J24.40 110.25,5.08 ; J24.40 109.22,4.05 ; J24.40 108.19,5.08 ; J24.40 109.22,6.11 ; J7.G4 38.99,61.24 ; J7.G4 36.25,61.24 ; J7.G4 37.62,62.61 ; J7.G4 37.62,59.87 ; 117.6,12.19 J20.3 ; J20.3 119.09,13.31 ; J20.3 119.09,11.07 ; J20.3 120.58,12.19 ; 48.84,49.88 J10.3 ; J10.3 48.84,51.82 ; J10.3 49.81,50.85 ; J10.3 47.88,50.85 ; J20.2 122.14,8.85 ; J20.2 121.02,7.37 ; J20.2 122.14,5.88 ; J20.2 123.26,7.37 ; J1.2 85.41,10.79 ; J1.2 83.25,10.79 ; J1.2 84.33,9.72 ; J1.2 84.33,11.87 ; 59.93,64.77 J5.40 ; J5.40 60.96,63.74 ; J5.40 61.99,64.77 ; J5.40 60.96,65.8 ; 32.54,40.44 J13.G3 ; J13.G3 32.54,43.18 ; J13.G3 31.17,41.81 ; J13.G3 33.91,41.81 ; 66.49,59.05 J3.7 ; J3.7 68.64,59.05 ; J3.7 67.56,60.13 ; J3.7 67.56,57.98 ; 60.96,1.51 J24.1 ; J24.1 61.99,2.54 ; J24.1 60.96,3.57 ; J24.1 59.93,2.54 ; 31.17,46.89 J13.G1 ; J13.G1 32.54,48.26 ; J13.G1 32.54,45.52 ; J13.G1 33.91,46.89 ; 80.71,10.79 J1.3 ; J1.3 82.87,10.79 ; J1.3 81.79,11.87 ; J1.3 81.79,9.72 ; 37.62,45.52 J13.G2 ; J13.G2 38.99,46.89 ; J13.G2 36.25,46.89 ; J13.G2 37.62,48.26 ; 114.68,45.64 J25.2 ; J25.2 115.65,46.61 ; J25.2 113.71,46.61 ; J25.2 114.68,47.58 ; J14.17 109.57,48.77 ; 36.25,41.81 J13.G4 ; J13.G4 37.62,43.18 ; J13.G4 37.62,40.44 ; J13.G4 38.99,41.81 ; J14.15 109.57,47.5 ; J8.6 15.88,55.42 ; J8.6 16.94,54.36 ; J8.6 15.88,53.29 ; J8.6 14.81,54.36 ; J7.G2 37.62,67.69 ; J7.G2 38.99,66.32 ; J7.G2 37.62,64.95 ; J7.G2 36.25,66.32 ; J16.8 24.77,24.45 ; J16.8 23.69,23.37 ; J16.8 24.77,22.29 ; J16.8 25.84,23.37 ; 15.88,4.01 J21.6 ; J21.6 16.94,5.08 ; J21.6 15.88,6.15 ; J21.6 14.81,5.08 ; 32.54,59.87 J7.G3 ; J7.G3 33.91,61.24 ; J7.G3 31.17,61.24 ; J7.G3 32.54,62.61 ; J14.3 109.57,39.88 ; J14.9 109.57,43.69
  L03_SIG1 w0.381: 67.56,57.98 J3.7 ; J3.7 66.49,59.05 ; J3.7 68.64,59.05 ; J3.7 67.56,60.13 ; 108.19,5.08 J24.40 ; J24.40 109.22,6.11 ; J24.40 110.25,5.08 ; J24.40 109.22,4.05 ; 60.96,63.74 J5.40 ; J5.40 60.96,65.8 ; J5.40 61.99,64.77 ; J5.40 59.93,64.77 ; J13.G3 33.91,41.81 ; J13.G3 32.54,43.18 ; J13.G3 32.54,40.44 ; J13.G3 31.17,41.81 ; 54.64,60.67 TP1.1 ; TP1.1 54.64,62.83 ; TP1.1 53.56,61.75 ; TP1.1 55.71,61.75 ; 47.88,50.85 J10.3 ; J10.3 48.84,51.82 ; J10.3 49.81,50.85 ; 114.68,45.64 J25.2 ; J25.2 115.65,46.61 ; J25.2 113.71,46.61 ; J25.2 114.68,47.58 ; 32.54,45.52 J13.G1 ; J13.G1 32.54,48.26 ; J13.G1 31.17,46.89 ; J13.G1 33.91,46.89 ; J16.8 24.77,24.45 ; J16.8 23.69,23.37 ; J16.8 25.84,23.37 ; J16.8 24.77,22.29 ; 36.25,41.81 J13.G4 ; J13.G4 37.62,43.18 ; J13.G4 37.62,40.44 ; J13.G4 38.99,41.81 ; 117.6,12.19 J20.3 ; J20.3 119.09,13.31 ; J20.3 120.58,12.19 ; J20.3 119.09,11.07 ; 100.06,29.11 TP8.1 98.98,30.19 ; J20.2 123.26,7.37 ; J20.2 122.14,8.85 ; J20.2 121.02,7.37 ; J20.2 122.14,5.88 ; R1.1 120.62,64.64 ; R1.1 121.52,63.74 ; R1.1 120.62,62.84 ; R1.1 119.72,63.74 ; J7.G3 32.54,62.61 ; J7.G3 31.17,61.24 ; J7.G3 33.91,61.24 ; J12.8 24.77,47.31 ; J12.8 24.77,45.15 ; J12.8 25.84,46.23 ; J5.1 109.22,68.34 ; J5.1 108.19,67.31 ; J5.1 110.25,67.31 ; J5.1 109.22,66.28 ; J14.9 109.57,43.69 ; 14.81,54.36 J8.6 ; J8.6 15.88,53.29 ; J8.6 15.88,55.42 ; J8.6 16.94,54.36 ; 36.25,66.32 J7.G2 ; J7.G2 38.99,66.32 ; J7.G2 37.62,67.69 ; J7.G2 37.62,64.95 ; J14.19 109.57,50.04 ; J14.15 109.57,47.5 ; 36.25,46.89 J13.G2 ; J13.G2 37.62,45.52 ; J13.G2 38.99,46.89 ; J13.G2 37.62,48.26 ; J7.G4 37.62,62.61 ; J7.G4 38.99,61.24 ; J7.G4 36.25,61.24 ; 32.54,64.95 J7.G1 ; J7.G1 32.54,67.69 ; J7.G1 33.91,66.32 ; J7.G1 31.17,66.32 ; 84.33,11.87 J1.2 84.33,9.72 ; 81.79,9.72 J1.3 81.79,11.87 ; J24.1 61.99,2.54 ; J24.1 60.96,1.51 ; J24.1 59.93,2.54 ; J14.17 109.57,48.77 ; J14.3 109.57,39.88 ; J14.5 109.57,41.15
  L04_SIG2 w0.381: 109.22,66.28 J5.1 ; J5.1 110.25,67.31 ; J5.1 108.19,67.31 ; J5.1 109.22,68.34 ; TP1.1 55.71,61.75 ; TP1.1 54.64,60.67 ; TP1.1 54.64,62.83 ; TP1.1 53.56,61.75 ; J20.3 119.09,13.31 ; J20.3 117.6,12.19 ; J20.3 120.58,12.19 ; J20.3 119.09,11.07 ; R1.1 121.52,63.74 ; R1.1 120.62,64.64 ; R1.1 119.72,63.74 ; R1.1 120.62,62.84 ; 37.62,64.95 J7.G2 ; J7.G2 37.62,67.69 ; J7.G2 38.99,66.32 ; J7.G2 36.25,66.32 ; 31.17,46.89 J13.G1 ; J13.G1 32.54,48.26 ; J13.G1 32.54,45.52 ; J13.G1 33.91,46.89 ; J7.G1 32.54,67.69 ; J7.G1 33.91,66.32 ; J7.G1 31.17,66.32 ; J7.G1 32.54,64.95 ; J25.2 115.65,46.61 ; J25.2 113.71,46.61 ; J25.2 114.68,47.58 ; J25.2 114.68,45.64 ; 37.62,45.52 J13.G2 ; J13.G2 38.99,46.89 ; J13.G2 36.25,46.89 ; J13.G2 37.62,48.26 ; 32.54,59.87 J7.G3 ; J7.G3 31.17,61.24 ; J7.G3 33.91,61.24 ; J7.G3 32.54,62.61 ; 41.26,4.37 TP13.1 ; TP13.1 42.34,5.45 ; TP13.1 43.42,4.37 ; TP13.1 42.34,3.29 ; J7.G4 37.62,62.61 ; J7.G4 36.25,61.24 ; J7.G4 37.62,59.87 ; J7.G4 38.99,61.24 ; 108.19,5.08 J24.40 ; J24.40 110.25,5.08 ; J24.40 109.22,6.11 ; J24.40 109.22,4.05 ; J10.3 48.84,51.82 ; J10.3 47.88,50.85 ; J10.3 48.84,49.88 ; J10.3 49.81,50.85 ; 80.71,10.79 J1.3 ; J1.3 81.79,11.87 ; J1.3 81.79,9.72 ; J1.3 82.87,10.79 ; J20.2 122.14,8.85 ; J20.2 122.14,5.88 ; J20.2 123.26,7.37 ; J20.2 121.02,7.37 ; J14.17 109.57,48.77 ; 59.93,2.54 J24.1 ; J24.1 60.96,3.57 ; J24.1 61.99,2.54 ; J24.1 60.96,1.51 ; 59.93,64.77 J5.40 61.99,64.77 ; 83.25,10.79 J1.2 ; J1.2 85.41,10.79 ; J1.2 84.33,9.72 ; J1.2 84.33,11.87 ; 97.91,29.11 TP8.1 ; TP8.1 98.98,28.03 ; TP8.1 100.06,29.11 ; TP8.1 98.98,30.19 ; J13.G4 38.99,41.81 ; J13.G4 37.62,43.18 ; J13.G4 36.25,41.81 ; J13.G4 37.62,40.44 ; 15.88,4.01 J21.6 ; J21.6 14.81,5.08 ; J21.6 15.88,6.15 ; J14.15 109.57,47.5 ; 24.77,45.15 J12.8 24.77,47.31 ; 32.54,40.44 J13.G3 ; J13.G3 32.54,43.18 ; J13.G3 33.91,41.81 ; J13.G3 31.17,41.81 ; 37.21,3.2 J23.3 ; J23.3 37.21,5.54 ; J23.3 36.04,4.37 ; J23.3 38.38,4.37 ; 67.56,60.13 J3.7 67.56,57.98 ; J14.5 109.57,41.15 ; 15.88,55.42 J8.6 15.88,53.29 ; J14.3 109.57,39.88 ; 109.57,50.04 J14.19 108.33,50.78 ; J14.9 109.57,43.69
  BOTTOM w0.229: C83.2 90.78,20.35 90.78,20.35 ; 90.93,20.4 91.11,20.58 U8.6
  BOTTOM w0.254: v1(94.67,19.51) 94.67,19.89 94.48,20.08 U8.15 ; v1(91.74,19.08) 92.21,19.54 U8.4
  BOTTOM w0.292: R133.1 77.42,16.46 v1(77.24,16.28) ; R130.2 67.88,16.84 v1(67.59,16.55) ; 86.07,31.46 86,31.53 U5.2 ; R139.2 v1(80.7,14.41) ; R127.2 v1(77.91,18.31) ; R135.1 v1(68.23,15.01)
  BOTTOM w0.305: U8.10 92.96,22.96 v1(93.01,23.01)
  BOTTOM w0.381: 42.34,3.29 TP13.1 ; TP13.1 43.42,4.37 ; TP13.1 41.26,4.37 ; TP13.1 42.34,5.45 ; R129.2 v1(47.25,18.17) ; R129.2 46.83,17.45 ; R129.2 47.25,16.96 ; 109.85,33.22 D2.A ; D2.A 110.69,34.44 ; D2.A 109.01,34.44 ; D2.A 109.85,35.66 ; C4.2 88.29,44.93 ; C4.2 87.76,45.72 v1(88.04,46) ; C4.2 87.23,44.93 ; R130.2 68.23,17.33 ; 32.54,59.87 J7.G3 ; J7.G3 32.54,62.61 ; J7.G3 33.91,61.24 ; J7.G3 31.17,61.24 ; J20.3 119.09,13.31 ; J20.3 117.6,12.19 ; J20.3 120.58,12.19 ; J20.3 119.09,11.07 ; C23.2 v1(81.18,35.92) ; C23.2 81.18,34.52 ; C23.2 80.68,35.05 ; R115.1 121.39,22.74 ; R115.1 120.98,22.25 ; R115.1 121.39,21.76 ; v1(95.15,38.3) 95.22,38.23 C56.2 ; Q10.S 124.06,14.35 ; Q10.S 124.06,13.22 ; Q10.S 124.58,13.78 ; Q10.S 123.55,13.78 ; 121.34,20.45 C79.2 ; C79.2 120.84,20.98 ; C79.2 121.34,21.51 ; J14.5 109.57,41.15 ; C90.2 91.97,17.17 ; C90.2 90.91,17.17 ; C90.2 91.44,16.69 ; 60.96,1.51 J24.1 ; J24.1 61.99,2.54 ; J24.1 59.93,2.54 ; C56.2 95.22,36.94 ; C56.2 95.72,37.47 ; 37.21,3.2 J23.3 ; J23.3 37.21,5.54 ; J23.3 36.04,4.37 ; J23.3 38.38,4.37 ; J14.17 109.57,48.77 ; J7.G4 37.62,62.61 ; J7.G4 36.25,61.24 ; J7.G4 38.99,61.24 ; J7.G4 37.62,59.87 ; 95.74,20.22 C84.2 v1(96.98,20.22) ; J16.8 25.84,23.37 ; J16.8 24.77,24.45 ; J16.8 23.69,23.37 ; J16.8 24.77,22.29 ; TP8.1 98.98,30.19 ; TP8.1 97.91,29.11 ; TP8.1 100.06,29.11 ; TP8.1 98.98,28.03 ; 80.71,33.07 C58.2 ; C58.2 v1(81.21,33.93) ; C58.2 81.21,32.54 ; C86.2 87.81,19.8 ; C86.2 86.87,19.01 ; C86.2 85.92,19.8 ; v1(84.53,32.61) U5.H v1(84.53,30.94) ; C43.2 44.34,56.9 ; C43.2 v1(43.81,56.06) ; C43.2 43.29,56.9 ; 81.18,41.51 C8.2 80.68,42.04 ; 70.37,31.82 C59.2 69.7,32.54 ; v1(71.15,15.39) R140.2 71.15,14.16 ; C28.2 93.33,32.16 ; C28.2 92.83,32.68 ; C28.2 v1(92.83,31.42) ; U7.3 118.43,30.25 ; U7.3 v1(117.25,30.25) ; U7.3 117.99,29.83 ; U7.3 117.99,30.67 ; R146.2 v1(60.66,12.7) ; R146.2 61.3,12.21 ; R146.2 61.3,13.19 ; 91.04,44.93 C6.2 ; C6.2 91.57,45.43 ; C6.2 92.3,44.93 v1(92.35,44.98) ; 108.19,67.31 J5.1 ; J5.1 109.22,66.28 ; J5.1 110.25,67.31 ; J5.1 109.22,68.34 ; 36.25,41.81 J13.G4 ; J13.G4 38.99,41.81 ; J13.G4 37.62,40.44 ; J13.G4 37.62,43.18 ; J20.2 123.26,7.37 ; J20.2 122.14,5.88 ; J20.2 122.14,8.85 ; J20.2 121.02,7.37 ; 31.17,46.89 J13.G1 ; J13.G1 33.91,46.89 ; J13.G1 32.54,48.26 ; J13.G1 32.54,45.52 ; J7.G1 33.91,66.32 ; J7.G1 32.54,67.69 ; J7.G1 32.54,64.95 ; J7.G1 31.17,66.32 ; R134.1 90.54,15.96 ; R134.1 90.04,15.54 ; R134.1 89.36,15.96 v1(89.18,15.77) ; C54.2 71.79,37.77 ; C54.2 71.07,37.1 ; C54.2 71.07,38.44 ; C44.2 54.72,51.58 ; C44.2 53.28,51.58 ; C44.2 54,52.12 v1(54.33,52.45) ; 85.65,19.8 C87.2 84.71,19.01 ; C66.1 74.37,26.36 ; C66.1 73.31,26.36 ; C66.1 73.84,26.86 ; v1(101.2,30.18) R98.1 v1(100.58,29.49) ; 24.77,45.15 J12.8 ; J12.8 25.84,46.23 ; J12.8 24.77,47.31 ; J12.8 23.69,46.23 ; 89.64,20.35 C83.2 90.17,19.85 ; 107.12,29.3 Q2.G ; v1(93.85,16.71) 93.8,16.76 R125.1 ; C93.2 v1(30.91,13.46) ; C93.2 30.91,12.2 ; C93.2 30.42,12.73 ; 32.54,40.44 J13.G3 ; J13.G3 33.91,41.81 ; J13.G3 32.54,43.18 ; J13.G3 31.17,41.81 ; 47.25,7.18 R154.2 ; R154.2 v1(47.25,8.39) ; R154.2 46.83,7.67 ; C81.2 101.27,20.06 ; C81.2 99.39,20.06 ; C81.2 100.33,19.26 ; 36.25,66.32 J7.G2 ; J7.G2 37.62,67.69 ; J7.G2 38.99,66.32 ; J7.G2 37.62,64.95 ; 79.82,31.7 C62.2 ; C62.2 80.32,32.23 ; C62.2 80.32,31.17 ; v1(113.38,21.33) R117.2 v1(112.57,21.95) ; 58.5,15.86 R138.2 57.78,15.37 ; 115.29,11.3 D6.2 ; D6.2 115.91,10.68 ; D6.2 v1(116.94,11.3) ; D6.2 v1(115.91,12.26) ; 57.84,14.3 R142.1 58.5,13.81 ; 48.68,40.81 C51.2 ; C51.2 48.58,41.43 v1(47.78,41.43) ; C51.2 49.35,41.53 ; C51.2 48.01,41.53 ; 61.61,32.71 R80.2 ; R80.2 60.94,33.43 ; R80.2 62.41,33.43 ; R80.2 61.61,34.14 ; R67.1 94.73,40.09 ; R67.1 93.74,40.09 ; R67.1 94.23,39.67 ; 67.81,15.82 R135.1 ; 36.25,46.89 J13.G2 ; J13.G2 37.62,45.52 ; J13.G2 38.99,46.89 ; J13.G2 37.62,48.26 ; 15.88,4.01 J21.6 ; J21.6 15.88,6.15 ; J21.6 14.81,5.08 ; J21.6 16.94,5.08 ; 80.63,20.52 C88.2 ; C88.2 80.63,22.41 ; C88.2 79.84,21.46 ; 114.68,45.64 J25.2 ; J25.2 114.68,47.58 ; J25.2 115.65,46.61 ; J25.2 113.71,46.61 ; 80.68,37.97 C20.2 ; C20.2 81.18,38.5 ; C20.2 v1(81.18,37.16) ; R83.2 119.46,32.37 ; R83.2 119.46,31.38 ; R83.2 v1(118.87,31.88) ; 122.2,57.51 C42.2 121.7,58.04 ; 98.17,19.26 C82.2 ; C82.2 99.11,20.06 ; C82.2 97.23,20.06 ; TP1.1 55.71,61.75 ; TP1.1 54.64,60.67 ; TP1.1 54.64,62.83 ; TP1.1 53.56,61.75 ; C53.2 65.09,40.28 ; C53.2 63.65,40.28 ; C53.2 64.43,41 ; v1(96.32,32.77) 96.29,32.79 R81.1 95.24,32.3 ; C92.2 v1(116.23,13.34) ; C92.2 115.18,12.62 ; C92.2 115.18,14.21 v1(115.34,14.38) ; 119.46,29.07 R99.2 v1(118.8,28.57) ; J14.3 109.57,39.88 ; C67.2 31.54,26.19 ; C67.2 30.48,26.19 ; C67.2 v1(31.01,27.08) ; 66.49,59.05 J3.7 ; J3.7 67.56,60.13 ; J3.7 68.64,59.05 ; J3.7 67.56,57.98 ; 94.36,19.73 U8.15 ; 108.33,50.78 J14.19 109.57,50.04 ; v1(86.84,30.63) C61.2 86.23,31.3 86.07,31.46 ; 119.48,24.27 D3.A 119.48,25.5 ; J24.40 110.25,5.08 ; J24.40 109.22,6.11 ; J24.40 108.19,5.08 ; J24.40 109.22,4.05 ; J5.40 61.99,64.77 ; J5.40 60.96,65.8 ; J5.40 60.96,63.74 ; J5.40 59.93,64.77 ; J14.15 109.57,47.5 ; R155.1 82.92,30.82 ; R155.1 82.42,30.4 ; R155.1 81.93,30.82 ; 15.88,53.29 J8.6 ; J8.6 16.94,54.36 ; J8.6 14.81,54.36 ; J8.6 15.88,55.42 ; v1(59.21,28.47) 59.33,28.6 C63.2 59.33,30.04 ; J14.9 109.57,43.69 ; 127.38,41.35 D1.A ; D1.A 126.86,41.96 ; D1.A v1(128.09,41.96) ; 88.77,19.28 C85.2 ; C85.2 88.05,19.95 ; C85.2 89.49,19.95 ; R150.1 124.42,12.79 ; R150.1 124,12.29 ; R150.1 124.42,11.8 ; C65.2 118.35,25.44 ; 84.47,44.62 R62.1 v1(84.96,45.24) ; v1(113.24,16.93) R132.2 v1(112.52,17.6) ; C52.2 v1(127.46,40.54) ; C52.2 126.69,41.07 ; C52.2 126.69,40.01 ; 77.49,17.48 R127.2 ; 101.55,20.06 C80.2 ; C80.2 103.43,20.06 ; C80.2 102.49,19.26 ; J10.3 48.84,51.82 ; J10.3 48.84,49.88 ; J10.3 49.81,50.85 ; 85.33,31.16 U5.2 ; 69.6,47.62 C46.2 70.66,47.62 ; 64.82,41.15 C50.2 ; 77.91,15.97 R133.1
  BOTTOM w0.508: C8.2 v1(81.18,42.83) ; C46.2 70.13,48.13 ; C59.2 v1(71.27,32.54) ; v1(117.63,24.41) C65.2 v1(116.62,25.44) ; v1(63.4,41.94) 63.65,41.68 C50.2 ; v1(120.29,24.88) D3.A v1(118.64,24.88) ; C45.2 v1(71.53,48.92) ; v1(70.15,37.74) 70.18,37.77 C54.2 ; C42.2 v1(122.2,58.95)
  vias: v1(8.15,11.13) v1(8.28,7.52) v1(8.89,20.65) v1(9.3,50.06) v1(10.06,44.35) v1(10.44,48.92) v1(10.72,11.23) v1(10.95,58.45) v1(11.89,20.78) v1(11.96,26.19) v1(13.11,58.45) v1(13.36,44.35) v1(14.12,7.26) v1(14.63,47.78) v1(15.01,29.62) v1(15.9,58.57) v1(16.15,26.19) v1(16.15,21.49) v1(16.15,7.65) v1(16.54,11.46) v1(16.92,62.89) v1(17.93,30.25) v1(18.31,48.03) v1(18.57,44.09) v1(18.57,20.98) v1(19.46,7.26) v1(19.58,26.95) v1(20.35,21.62) v1(21.23,62.76) v1(22.12,47.9) v1(22.38,41.94) v1(23.01,30.51) v1(23.77,36.6) v1(24.66,43.33) v1(24.92,26.19) v1(24.92,8.66) v1(26.31,11.33) v1(26.95,62.13) v1(29.62,59.59) v1(36.47,14.63) v1(36.47,13.74) v1(36.47,12.85) v1(37.47,14.63) v1(37.47,12.85) v1(51.68,40.5) v1(53.62,30.61) v1(56.92,30.35) v1(59.33,43.21) v1(59.33,41.94) v1(59.33,40.67) v1(59.33,39.4) v1(60.35,43.21) v1(60.35,41.94) v1(60.35,40.67) v1(60.35,39.4) v1(61.37,43.21) v1(61.37,41.94) v1(61.37,40.67) v1(61.37,39.4) v1(62,30.43) v1(62.28,56.46) v1(62.38,43.21) v1(62.38,41.94) v1(62.38,40.67) v1(62.38,39.4) v1(63.4,43.21) v1(63.4,40.67) v1(63.4,39.4) v1(63.91,30.4) v1(65.68,29.11) v1(65.68,28.5) v1(68.76,19) v1(68.83,18.08) v1(69.37,31.52) v1(70.1,38.36) v1(72.39,20.19) v1(73.13,26.34) v1(73.28,20.19) v1(74.3,20.19) v1(75.31,20.45) v1(79.27,22.12) v1(79.4,22.76) v1(79.76,32.39) v1(80.16,22.76) v1(80.92,22.76) v1(82.35,30.07) v1(84.61,18.82) v1(85.75,40.54) v1(85.75,39.52) v1(85.75,35.46) v1(85.75,18.82) v1(86.77,40.54) v1(86.77,39.52) v1(86.77,38.51) v1(86.77,37.49) v1(86.77,36.47) v1(87,18.67) v1(87.78,39.52) v1(87.78,38.51) v1(87.78,37.49) v1(87.78,36.47) v1(88.8,39.52) v1(88.8,38.51) v1(88.8,37.49) v1(88.8,36.47) v1(89.74,19.46) v1(89.81,40.54) v1(89.81,39.52) v1(89.81,38.51) v1(89.81,37.49) v1(89.81,36.47) v1(89.81,35.46) v1(90.37,19.46) v1(90.83,40.54) v1(90.83,39.52) v1(90.83,38.51) v1(90.83,36.47) v1(90.83,35.46) v1(91.72,16.41) v1(93.5,39.65) v1(97.21,18.92) v1(98.12,18.92) v1(100.3,18.92) v1(101.42,18.92) v1(102.51,18.92) v1(103.3,54.86) v1(103.45,18.9) v1(106.83,29.26) v1(108.15,22.56) v1(111.02,35.2) v1(111.02,34.06) v1(112.45,27.81) v1(120.42,22.25) v1(120.42,20.98) v1(120.8,33.43) v1(121.13,26.67) v1(121.31,33.05) v1(121.67,26.37) v1(123.22,13.77) v1(123.67,12.32) v2(56.9,26.42) v2(56.9,24.89) v2(56.9,23.37) v2(56.9,21.84) v2(56.9,20.32) v2(56.9,18.8) v2(56.9,17.27) v2(58.42,26.42) v2(58.42,24.89) v2(58.42,23.37) v2(58.42,21.84) v2(58.42,20.32) v2(58.42,18.8) v2(58.42,17.27) v2(59.94,26.42) v2(59.94,24.89) v2(59.94,23.37) v2(59.94,21.84) v2(59.94,20.32) v2(59.94,18.8) v2(59.94,17.27) v2(61.47,26.42) v2(61.47,24.89) v2(61.47,23.37) v2(61.47,21.84) v2(61.47,20.32) v2(61.47,18.8) v2(61.47,17.27) v2(62.99,26.42) v2(62.99,24.89) v2(62.99,23.37) v2(62.99,21.84) v2(62.99,20.32) v2(62.99,18.8) v2(62.99,17.27)
